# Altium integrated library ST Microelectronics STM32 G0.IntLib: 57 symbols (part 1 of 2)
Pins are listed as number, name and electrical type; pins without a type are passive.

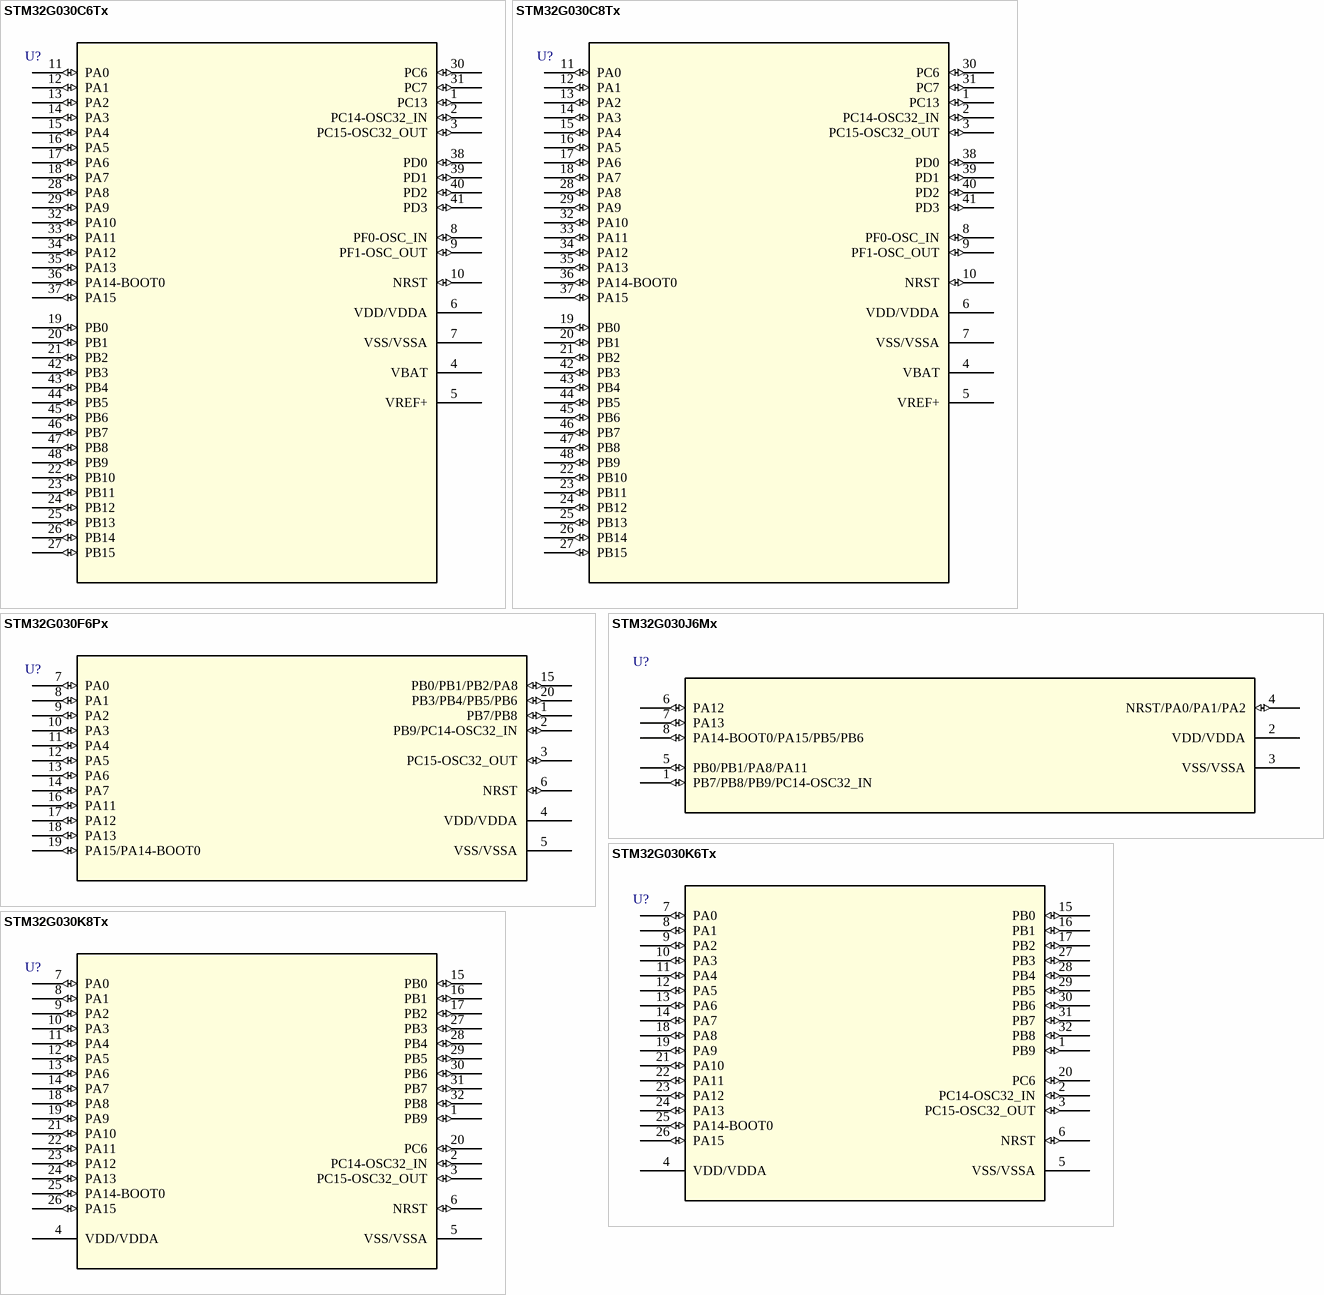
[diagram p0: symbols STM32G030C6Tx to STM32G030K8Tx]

## STM32G030C6Tx
designator U?
The STM32G030x6/x8 mainstream microcontrollers are based on high-performance Arm® Cortex®-M0+ 32-bit RISC core operating at up to 64 MHz frequency. / 32K Flash and 8K RAM with 48pin LQFP 7x7x0.55  package; Manufacturer_Part_Number: stm32g0_lqfp48_t2; Vendor: STMicroelectronics
footprint LQFP48
pins: 1 PC13 (io), 2 PC14-OSC32_IN (io), 3 PC15-OSC32_OUT (io), 4 VBAT (power), 5 VREF+ (power), 6 VDD/VDDA (power), 7 VSS/VSSA (power), 8 PF0-OSC_IN (io), 9 PF1-OSC_OUT (io), 10 NRST (io), 11 PA0 (io), 12 PA1 (io), 13 PA2 (io), 14 PA3 (io), 15 PA4 (io), 16 PA5 (io), 17 PA6 (io), 18 PA7 (io), 19 PB0 (io), 20 PB1 (io), 21 PB2 (io), 22 PB10 (io), 23 PB11 (io), 24 PB12 (io), 25 PB13 (io), 26 PB14 (io), 27 PB15 (io), 28 PA8 (io), 29 PA9 (io), 30 PC6 (io), 31 PC7 (io), 32 PA10 (io), 33 PA11 (io), 34 PA12 (io), 35 PA13 (io), 36 PA14-BOOT0 (io), 37 PA15 (io), 38 PD0 (io), 39 PD1 (io), 40 PD2 (io), 41 PD3 (io), 42 PB3 (io), 43 PB4 (io), 44 PB5 (io), 45 PB6 (io), 46 PB7 (io), 47 PB8 (io), 48 PB9 (io)

## STM32G030C8Tx
designator U?
The STM32G030x6/x8 mainstream microcontrollers are based on high-performance Arm® Cortex®-M0+ 32-bit RISC core operating at up to 64 MHz frequency. / 64K Flash and 8K RAM with 48pin LQFP 7x7x0.55 package; Manufacturer_Part_Number: stm32g0_lqfp48_t2; Vendor: STMicroelectronics
footprint LQFP48
pins: 1 PC13 (io), 2 PC14-OSC32_IN (io), 3 PC15-OSC32_OUT (io), 4 VBAT (power), 5 VREF+ (power), 6 VDD/VDDA (power), 7 VSS/VSSA (power), 8 PF0-OSC_IN (io), 9 PF1-OSC_OUT (io), 10 NRST (io), 11 PA0 (io), 12 PA1 (io), 13 PA2 (io), 14 PA3 (io), 15 PA4 (io), 16 PA5 (io), 17 PA6 (io), 18 PA7 (io), 19 PB0 (io), 20 PB1 (io), 21 PB2 (io), 22 PB10 (io), 23 PB11 (io), 24 PB12 (io), 25 PB13 (io), 26 PB14 (io), 27 PB15 (io), 28 PA8 (io), 29 PA9 (io), 30 PC6 (io), 31 PC7 (io), 32 PA10 (io), 33 PA11 (io), 34 PA12 (io), 35 PA13 (io), 36 PA14-BOOT0 (io), 37 PA15 (io), 38 PD0 (io), 39 PD1 (io), 40 PD2 (io), 41 PD3 (io), 42 PB3 (io), 43 PB4 (io), 44 PB5 (io), 45 PB6 (io), 46 PB7 (io), 47 PB8 (io), 48 PB9 (io)

## STM32G030F6Px
designator U?
The STM32G030x6/x8 mainstream microcontrollers are based on high-performance Arm® Cortex®-M0+ 32-bit RISC core operating at up to 64 MHz frequency. / 32K Flash and 8K RAM with 20pin TSSOP 6.4x4.4mm package; Manufacturer_Part_Number: stm32g0_tssop20_t1; Vendor: STMicroelectronics
footprint TSSOP20
pins: 1 PB7/PB8 (io), 2 PB9/PC14-OSC32_IN (io), 3 PC15-OSC32_OUT (io), 4 VDD/VDDA (power), 5 VSS/VSSA (power), 6 NRST (io), 7 PA0 (io), 8 PA1 (io), 9 PA2 (io), 10 PA3 (io), 11 PA4 (io), 12 PA5 (io), 13 PA6 (io), 14 PA7 (io), 15 PB0/PB1/PB2/PA8 (io), 16 PA11 (io), 17 PA12 (io), 18 PA13 (io), 19 PA15/PA14-BOOT0 (io), 20 PB3/PB4/PB5/PB6 (io)

## STM32G030J6Mx
designator U?
The STM32G030x6/x8 mainstream microcontrollers are based on high-performance Arm® Cortex®-M0+ 32-bit RISC core operating at up to 64 MHz frequency. / 32K Flash and 8K RAM with 8pin SON 4.9x6 mm package; Manufacturer_Part_Number: stm32g0_so8_t1; Vendor: STMicroelectronics
footprint SO-8
pins: 1 PB7/PB8/PB9/PC14-OSC32_IN (io), 2 VDD/VDDA (power), 3 VSS/VSSA (power), 4 NRST/PA0/PA1/PA2 (io), 5 PB0/PB1/PA8/PA11 (io), 6 PA12 (io), 7 PA13 (io), 8 PA14-BOOT0/PA15/PB5/PB6 (io)

## STM32G030K6Tx
designator U?
The STM32G030x6/x8 mainstream microcontrollers are based on high-performance Arm® Cortex®-M0+ 32-bit RISC core operating at up to 64 MHz frequency. / 32K Flash and 8K RAM with 32pin LQFP 7x7x1.4 package; Manufacturer_Part_Number: STM32G0_LQFP32_T2; Vendor: STMicroelectronics
footprint LQFP-32
pins: 1 PB9 (io), 2 PC14-OSC32_IN (io), 3 PC15-OSC32_OUT (io), 4 VDD/VDDA (power), 5 VSS/VSSA (power), 6 NRST (io), 7 PA0 (io), 8 PA1 (io), 9 PA2 (io), 10 PA3 (io), 11 PA4 (io), 12 PA5 (io), 13 PA6 (io), 14 PA7 (io), 15 PB0 (io), 16 PB1 (io), 17 PB2 (io), 18 PA8 (io), 19 PA9 (io), 20 PC6 (io), 21 PA10 (io), 22 PA11 (io), 23 PA12 (io), 24 PA13 (io), 25 PA14-BOOT0 (io), 26 PA15 (io), 27 PB3 (io), 28 PB4 (io), 29 PB5 (io), 30 PB6 (io), 31 PB7 (io), 32 PB8 (io)

## STM32G030K8Tx
designator U?
The STM32G030x6/x8 mainstream microcontrollers are based on high-performance Arm® Cortex®-M0+ 32-bit RISC core operating at up to 64 MHz frequency. / 64K Flash and 8K RAM with 32pin LQFP 7x7x1.4 package; Manufacturer_Part_Number: STM32G0_LQFP32_T2; Vendor: STMicroelectronics
footprint LQFP-32
pins: 1 PB9 (io), 2 PC14-OSC32_IN (io), 3 PC15-OSC32_OUT (io), 4 VDD/VDDA (power), 5 VSS/VSSA (power), 6 NRST (io), 7 PA0 (io), 8 PA1 (io), 9 PA2 (io), 10 PA3 (io), 11 PA4 (io), 12 PA5 (io), 13 PA6 (io), 14 PA7 (io), 15 PB0 (io), 16 PB1 (io), 17 PB2 (io), 18 PA8 (io), 19 PA9 (io), 20 PC6 (io), 21 PA10 (io), 22 PA11 (io), 23 PA12 (io), 24 PA13 (io), 25 PA14-BOOT0 (io), 26 PA15 (io), 27 PB3 (io), 28 PB4 (io), 29 PB5 (io), 30 PB6 (io), 31 PB7 (io), 32 PB8 (io)

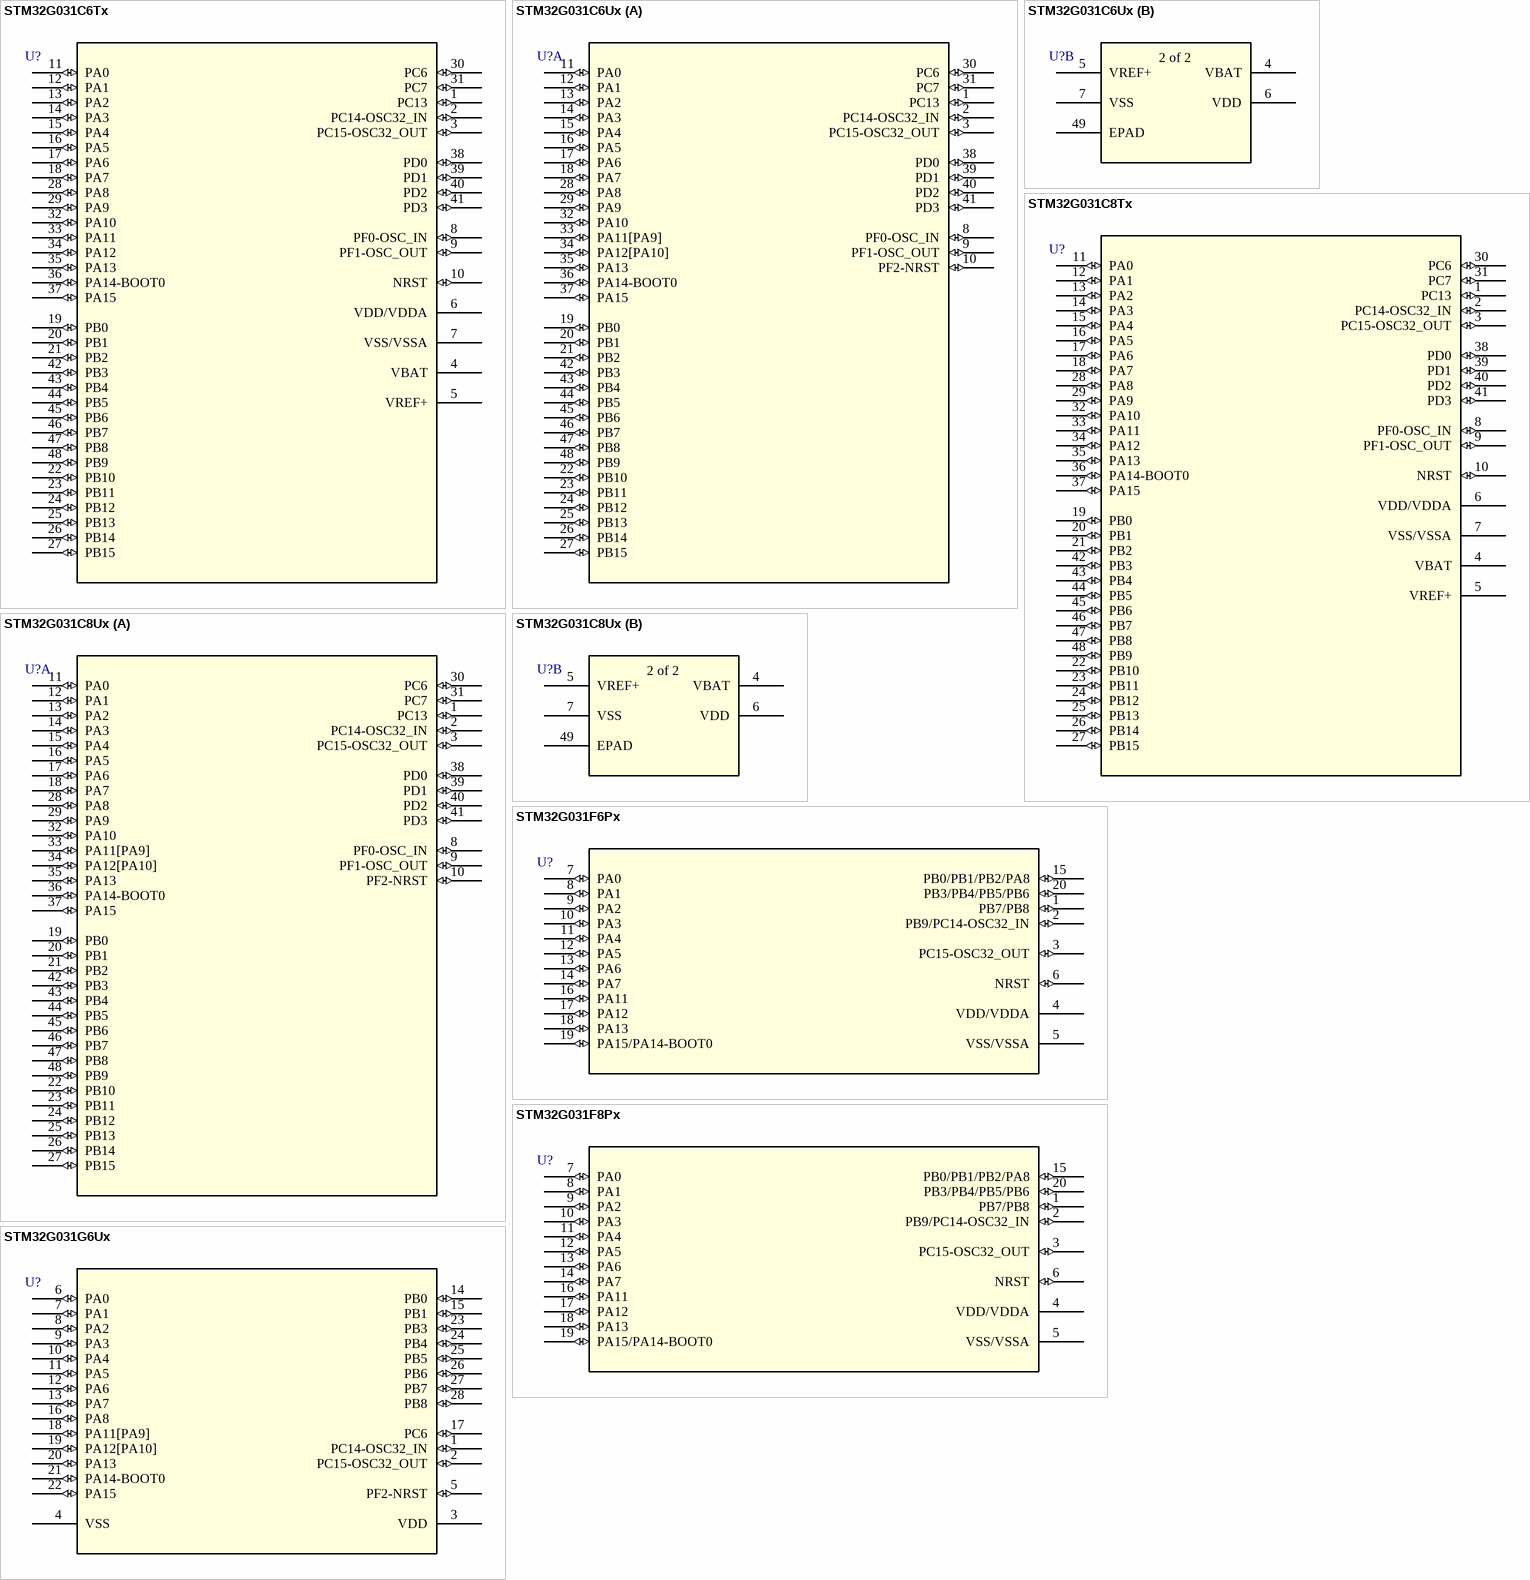
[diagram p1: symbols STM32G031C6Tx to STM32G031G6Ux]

## STM32G031C6Tx
designator U?
The STM32G031x4/x6/x8 mainstream microcontrollers are based on high-performance Arm® Cortex®-M0+ 32-bit RISC core operating at up to 64 MHz frequency. / 32 Kbytes of Flash program memory and 8 Kbytes of SRAM. With 48pin LQFP 7x7x1.4 package; Manufacturer_Part_Number: stm32g0_lqfp48_t2; Vendor: STMicroelectronics
footprint LQFP48
pins: 1 PC13 (io), 2 PC14-OSC32_IN (io), 3 PC15-OSC32_OUT (io), 4 VBAT (power), 5 VREF+ (power), 6 VDD/VDDA (power), 7 VSS/VSSA (power), 8 PF0-OSC_IN (io), 9 PF1-OSC_OUT (io), 10 NRST (io), 11 PA0 (io), 12 PA1 (io), 13 PA2 (io), 14 PA3 (io), 15 PA4 (io), 16 PA5 (io), 17 PA6 (io), 18 PA7 (io), 19 PB0 (io), 20 PB1 (io), 21 PB2 (io), 22 PB10 (io), 23 PB11 (io), 24 PB12 (io), 25 PB13 (io), 26 PB14 (io), 27 PB15 (io), 28 PA8 (io), 29 PA9 (io), 30 PC6 (io), 31 PC7 (io), 32 PA10 (io), 33 PA11 (io), 34 PA12 (io), 35 PA13 (io), 36 PA14-BOOT0 (io), 37 PA15 (io), 38 PD0 (io), 39 PD1 (io), 40 PD2 (io), 41 PD3 (io), 42 PB3 (io), 43 PB4 (io), 44 PB5 (io), 45 PB6 (io), 46 PB7 (io), 47 PB8 (io), 48 PB9 (io)

## STM32G031C6Ux
designator U?
The STM32G031x4/x6/x8 mainstream microcontrollers are based on high-performance Arm® Cortex®-M0+ 32-bit RISC core operating at up to 64 MHz frequency. / 32 Kbytes of Flash program memory and 8 Kbytes of SRAM. With 48pin UFQFPN 7x7x0.55 package; Manufacturer_Part_Number: stm32g0_ufqfpn48_t1; Built_By: EMA_Jessica; Vendor: STMicroelectronics
footprint UFQFPN48-7x7mm
part A pins: 1 PC13 (io), 2 PC14-OSC32_IN (io), 3 PC15-OSC32_OUT (io), 8 PF0-OSC_IN (io), 9 PF1-OSC_OUT (io), 10 PF2-NRST (io), 11 PA0 (io), 12 PA1 (io), 13 PA2 (io), 14 PA3 (io), 15 PA4 (io), 16 PA5 (io), 17 PA6 (io), 18 PA7 (io), 19 PB0 (io), 20 PB1 (io), 21 PB2 (io), 22 PB10 (io), 23 PB11 (io), 24 PB12 (io), 25 PB13 (io), 26 PB14 (io), 27 PB15 (io), 28 PA8 (io), 29 PA9 (io), 30 PC6 (io), 31 PC7 (io), 32 PA10 (io), 33 PA11[PA9] (io), 34 PA12[PA10] (io), 35 PA13 (io), 36 PA14-BOOT0 (io), 37 PA15 (io), 38 PD0 (io), 39 PD1 (io), 40 PD2 (io), 41 PD3 (io), 42 PB3 (io), 43 PB4 (io), 44 PB5 (io), 45 PB6 (io), 46 PB7 (io), 47 PB8 (io), 48 PB9 (io)
part B pins: 4 VBAT (power), 5 VREF+ (power), 6 VDD (power), 7 VSS (power), 49 EPAD

## STM32G031C8Tx
designator U?
The STM32G031x4/x6/x8 mainstream microcontrollers are based on high-performance Arm® Cortex®-M0+ 32-bit RISC core operating at up to 64 MHz frequency. / 64 Kbytes of Flash program memory and 8 Kbytes of SRAM. With 48pin LQFP  7x7x1.4  package; Manufacturer_Part_Number: stm32g0_lqfp48_t2; Vendor: STMicroelectronics
footprint LQFP48
pins: 1 PC13 (io), 2 PC14-OSC32_IN (io), 3 PC15-OSC32_OUT (io), 4 VBAT (power), 5 VREF+ (power), 6 VDD/VDDA (power), 7 VSS/VSSA (power), 8 PF0-OSC_IN (io), 9 PF1-OSC_OUT (io), 10 NRST (io), 11 PA0 (io), 12 PA1 (io), 13 PA2 (io), 14 PA3 (io), 15 PA4 (io), 16 PA5 (io), 17 PA6 (io), 18 PA7 (io), 19 PB0 (io), 20 PB1 (io), 21 PB2 (io), 22 PB10 (io), 23 PB11 (io), 24 PB12 (io), 25 PB13 (io), 26 PB14 (io), 27 PB15 (io), 28 PA8 (io), 29 PA9 (io), 30 PC6 (io), 31 PC7 (io), 32 PA10 (io), 33 PA11 (io), 34 PA12 (io), 35 PA13 (io), 36 PA14-BOOT0 (io), 37 PA15 (io), 38 PD0 (io), 39 PD1 (io), 40 PD2 (io), 41 PD3 (io), 42 PB3 (io), 43 PB4 (io), 44 PB5 (io), 45 PB6 (io), 46 PB7 (io), 47 PB8 (io), 48 PB9 (io)

## STM32G031C8Ux
designator U?
The STM32G031x4/x6/x8 mainstream microcontrollers are based on high-performance Arm® Cortex®-M0+ 32-bit RISC core operating at up to 64 MHz frequency. / 64 Kbytes of Flash program memory and 8 Kbytes of SRAM. With 48pin UFQFPN  7x7x0.55 package; Manufacturer_Part_Number: stm32g0_ufqfpn48_t1; Built_By: EMA_Jessica; Vendor: STMicroelectronics
footprint UFQFPN48-7x7mm
part A pins: 1 PC13 (io), 2 PC14-OSC32_IN (io), 3 PC15-OSC32_OUT (io), 8 PF0-OSC_IN (io), 9 PF1-OSC_OUT (io), 10 PF2-NRST (io), 11 PA0 (io), 12 PA1 (io), 13 PA2 (io), 14 PA3 (io), 15 PA4 (io), 16 PA5 (io), 17 PA6 (io), 18 PA7 (io), 19 PB0 (io), 20 PB1 (io), 21 PB2 (io), 22 PB10 (io), 23 PB11 (io), 24 PB12 (io), 25 PB13 (io), 26 PB14 (io), 27 PB15 (io), 28 PA8 (io), 29 PA9 (io), 30 PC6 (io), 31 PC7 (io), 32 PA10 (io), 33 PA11[PA9] (io), 34 PA12[PA10] (io), 35 PA13 (io), 36 PA14-BOOT0 (io), 37 PA15 (io), 38 PD0 (io), 39 PD1 (io), 40 PD2 (io), 41 PD3 (io), 42 PB3 (io), 43 PB4 (io), 44 PB5 (io), 45 PB6 (io), 46 PB7 (io), 47 PB8 (io), 48 PB9 (io)
part B pins: 4 VBAT (power), 5 VREF+ (power), 6 VDD (power), 7 VSS (power), 49 EPAD

## STM32G031F6Px
designator U?
The STM32G031x4/x6/x8 mainstream microcontrollers are based on high-performance Arm® Cortex®-M0+ 32-bit RISC core operating at up to 64 MHz frequency. / 32 Kbytes of Flash program memory and 8 Kbytes of SRAM. With 20pin TSSOP 6.4x4.4 package; Manufacturer_Part_Number: stm32g0_tssop20_t1; Vendor: STMicroelectronics
footprint TSSOP20
pins: 1 PB7/PB8 (io), 2 PB9/PC14-OSC32_IN (io), 3 PC15-OSC32_OUT (io), 4 VDD/VDDA (power), 5 VSS/VSSA (power), 6 NRST (io), 7 PA0 (io), 8 PA1 (io), 9 PA2 (io), 10 PA3 (io), 11 PA4 (io), 12 PA5 (io), 13 PA6 (io), 14 PA7 (io), 15 PB0/PB1/PB2/PA8 (io), 16 PA11 (io), 17 PA12 (io), 18 PA13 (io), 19 PA15/PA14-BOOT0 (io), 20 PB3/PB4/PB5/PB6 (io)

## STM32G031F8Px
designator U?
The STM32G031x4/x6/x8 mainstream microcontrollers are based on high-performance Arm® Cortex®-M0+ 32-bit RISC core operating at up to 64 MHz frequency. / 64 Kbytes of Flash program memory and 8 Kbytes of SRAM. With 20pin TSSOP 6.4x4.4 package; Manufacturer_Part_Number: stm32g0_tssop20_t1; Vendor: STMicroelectronics
footprint TSSOP20
pins: 1 PB7/PB8 (io), 2 PB9/PC14-OSC32_IN (io), 3 PC15-OSC32_OUT (io), 4 VDD/VDDA (power), 5 VSS/VSSA (power), 6 NRST (io), 7 PA0 (io), 8 PA1 (io), 9 PA2 (io), 10 PA3 (io), 11 PA4 (io), 12 PA5 (io), 13 PA6 (io), 14 PA7 (io), 15 PB0/PB1/PB2/PA8 (io), 16 PA11 (io), 17 PA12 (io), 18 PA13 (io), 19 PA15/PA14-BOOT0 (io), 20 PB3/PB4/PB5/PB6 (io)

## STM32G031G6Ux
designator U?
The STM32G031x4/x6/x8 mainstream microcontrollers are based on high-performance Arm® Cortex®-M0+ 32-bit RISC core operating at up to 64 MHz frequency. / 32 Kbytes of Flash program memory and 8 Kbytes of SRAM. With 28pin UFQFPN 4x4x0.55 package; Manufacturer_Part_Number: stm32g0_ufqfpn28_t1; Built_By: EMA_Jessica; Vendor: STMicroelectronics
footprint UFQFPN-28
pins: 1 PC14-OSC32_IN (io), 2 PC15-OSC32_OUT (io), 3 VDD (power), 4 VSS (power), 5 PF2-NRST (io), 6 PA0 (io), 7 PA1 (io), 8 PA2 (io), 9 PA3 (io), 10 PA4 (io), 11 PA5 (io), 12 PA6 (io), 13 PA7 (io), 14 PB0 (io), 15 PB1 (io), 16 PA8 (io), 17 PC6 (io), 18 PA11[PA9] (io), 19 PA12[PA10] (io), 20 PA13 (io), 21 PA14-BOOT0 (io), 22 PA15 (io), 23 PB3 (io), 24 PB4 (io), 25 PB5 (io), 26 PB6 (io), 27 PB7 (io), 28 PB8 (io)

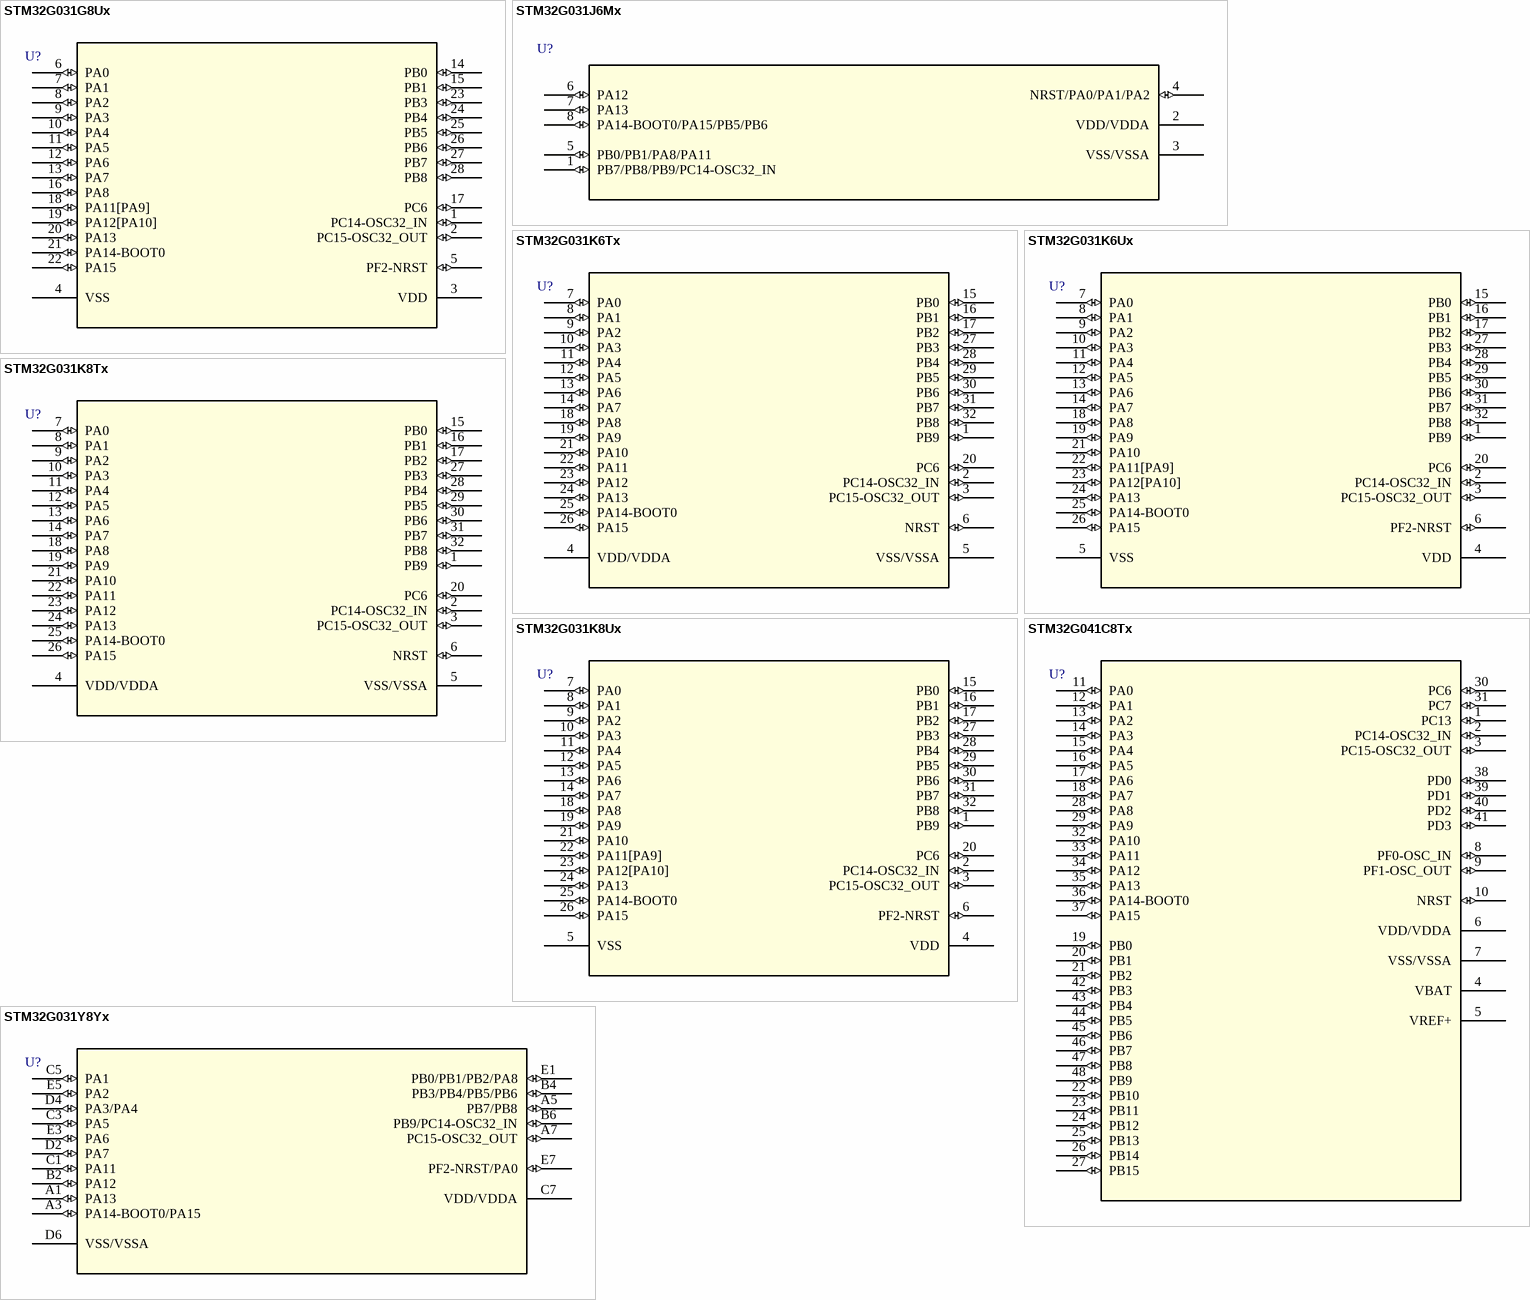
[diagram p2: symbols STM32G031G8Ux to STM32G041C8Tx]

## STM32G031G8Ux
designator U?
The STM32G031x4/x6/x8 mainstream microcontrollers are based on high-performance Arm® Cortex®-M0+ 32-bit RISC core operating at up to 64 MHz frequency. / 64 Kbytes of Flash program memory and 8 Kbytes of SRAM. With 28pin UFQFPN 4x4x0.55 package; Manufacturer_Part_Number: stm32g0_ufqfpn28_t1; Built_By: EMA_Jessica; Vendor: STMicroelectronics
footprint UFQFPN-28
pins: 1 PC14-OSC32_IN (io), 2 PC15-OSC32_OUT (io), 3 VDD (power), 4 VSS (power), 5 PF2-NRST (io), 6 PA0 (io), 7 PA1 (io), 8 PA2 (io), 9 PA3 (io), 10 PA4 (io), 11 PA5 (io), 12 PA6 (io), 13 PA7 (io), 14 PB0 (io), 15 PB1 (io), 16 PA8 (io), 17 PC6 (io), 18 PA11[PA9] (io), 19 PA12[PA10] (io), 20 PA13 (io), 21 PA14-BOOT0 (io), 22 PA15 (io), 23 PB3 (io), 24 PB4 (io), 25 PB5 (io), 26 PB6 (io), 27 PB7 (io), 28 PB8 (io)

## STM32G031J6Mx
designator U?
The STM32G031x4/x6/x8 mainstream microcontrollers are based on high-performance Arm® Cortex®-M0+ 32-bit RISC core operating at up to 64 MHz frequency. / 32 Kbytes of Flash program memory and 8 Kbytes of SRAM. With 28pin UFQFPN 4x4x0.55 package; Manufacturer_Part_Number: stm32g0_so8_t1; Vendor: STMicroelectronics
footprint SO-8
pins: 1 PB7/PB8/PB9/PC14-OSC32_IN (io), 2 VDD/VDDA (power), 3 VSS/VSSA (power), 4 NRST/PA0/PA1/PA2 (io), 5 PB0/PB1/PA8/PA11 (io), 6 PA12 (io), 7 PA13 (io), 8 PA14-BOOT0/PA15/PB5/PB6 (io)

## STM32G031K6Tx
designator U?
The STM32G031x4/x6/x8 mainstream microcontrollers are based on high-performance Arm® Cortex®-M0+ 32-bit RISC core operating at up to 64 MHz frequency. / 32 Kbytes of Flash program memory and 8 Kbytes of SRAM. With 32pin LQFP 7x7x1.4 package; Manufacturer_Part_Number: STM32G0_LQFP32_T2; Vendor: STMicroelectronics
footprint LQFP-32
pins: 1 PB9 (io), 2 PC14-OSC32_IN (io), 3 PC15-OSC32_OUT (io), 4 VDD/VDDA (power), 5 VSS/VSSA (power), 6 NRST (io), 7 PA0 (io), 8 PA1 (io), 9 PA2 (io), 10 PA3 (io), 11 PA4 (io), 12 PA5 (io), 13 PA6 (io), 14 PA7 (io), 15 PB0 (io), 16 PB1 (io), 17 PB2 (io), 18 PA8 (io), 19 PA9 (io), 20 PC6 (io), 21 PA10 (io), 22 PA11 (io), 23 PA12 (io), 24 PA13 (io), 25 PA14-BOOT0 (io), 26 PA15 (io), 27 PB3 (io), 28 PB4 (io), 29 PB5 (io), 30 PB6 (io), 31 PB7 (io), 32 PB8 (io)

## STM32G031K6Ux
designator U?
The STM32G031x4/x6/x8 mainstream microcontrollers are based on high-performance Arm® Cortex®-M0+ 32-bit RISC core operating at up to 64 MHz frequency. / 32 Kbytes of Flash program memory and 8 Kbytes of SRAM. With 32pin UFQFPN  5x5x0.55  package; Manufacturer_Part_Number: stm32g0_ufqfpn32_t1; Built_By: EMA_Jessica; Vendor: STMicroelectronics
footprint UFQFPN-32
pins: 1 PB9 (io), 2 PC14-OSC32_IN (io), 3 PC15-OSC32_OUT (io), 4 VDD (power), 5 VSS (power), 6 PF2-NRST (io), 7 PA0 (io), 8 PA1 (io), 9 PA2 (io), 10 PA3 (io), 11 PA4 (io), 12 PA5 (io), 13 PA6 (io), 14 PA7 (io), 15 PB0 (io), 16 PB1 (io), 17 PB2 (io), 18 PA8 (io), 19 PA9 (io), 20 PC6 (io), 21 PA10 (io), 22 PA11[PA9] (io), 23 PA12[PA10] (io), 24 PA13 (io), 25 PA14-BOOT0 (io), 26 PA15 (io), 27 PB3 (io), 28 PB4 (io), 29 PB5 (io), 30 PB6 (io), 31 PB7 (io), 32 PB8 (io)

## STM32G031K8Tx
designator U?
The STM32G031x4/x6/x8 mainstream microcontrollers are based on high-performance Arm® Cortex®-M0+ 32-bit RISC core operating at up to 64 MHz frequency. / 64 Kbytes of Flash program memory and 8 Kbytes of SRAM. With 32pin LQFP 7x7x1.4 package; Manufacturer_Part_Number: STM32G0_LQFP32_T2; Vendor: STMicroelectronics
footprint LQFP-32
pins: 1 PB9 (io), 2 PC14-OSC32_IN (io), 3 PC15-OSC32_OUT (io), 4 VDD/VDDA (power), 5 VSS/VSSA (power), 6 NRST (io), 7 PA0 (io), 8 PA1 (io), 9 PA2 (io), 10 PA3 (io), 11 PA4 (io), 12 PA5 (io), 13 PA6 (io), 14 PA7 (io), 15 PB0 (io), 16 PB1 (io), 17 PB2 (io), 18 PA8 (io), 19 PA9 (io), 20 PC6 (io), 21 PA10 (io), 22 PA11 (io), 23 PA12 (io), 24 PA13 (io), 25 PA14-BOOT0 (io), 26 PA15 (io), 27 PB3 (io), 28 PB4 (io), 29 PB5 (io), 30 PB6 (io), 31 PB7 (io), 32 PB8 (io)

## STM32G031K8Ux
designator U?
The STM32G031x4/x6/x8 mainstream microcontrollers are based on high-performance Arm® Cortex®-M0+ 32-bit RISC core operating at up to 64 MHz frequency. / 64 Kbytes of Flash program memory and 8 Kbytes of SRAM. With 32pin UFQFPN  5x5x0.55  package; Manufacturer_Part_Number: stm32g0_ufqfpn32_t1; Built_By: EMA_Jessica; Vendor: STMicroelectronics
footprint UFQFPN-32
pins: 1 PB9 (io), 2 PC14-OSC32_IN (io), 3 PC15-OSC32_OUT (io), 4 VDD (power), 5 VSS (power), 6 PF2-NRST (io), 7 PA0 (io), 8 PA1 (io), 9 PA2 (io), 10 PA3 (io), 11 PA4 (io), 12 PA5 (io), 13 PA6 (io), 14 PA7 (io), 15 PB0 (io), 16 PB1 (io), 17 PB2 (io), 18 PA8 (io), 19 PA9 (io), 20 PC6 (io), 21 PA10 (io), 22 PA11[PA9] (io), 23 PA12[PA10] (io), 24 PA13 (io), 25 PA14-BOOT0 (io), 26 PA15 (io), 27 PB3 (io), 28 PB4 (io), 29 PB5 (io), 30 PB6 (io), 31 PB7 (io), 32 PB8 (io)

## STM32G031Y8Yx
designator U?
The STM32G031x4/x6/x8 mainstream microcontrollers are based on high-performance Arm® Cortex®-M0+ 32-bit RISC core operating at up to 64 MHz frequency. / 64 Kbytes of Flash program memory and 8 Kbytes of SRAM. With 18pin WLCSP  1.86x2.14  package; Manufacturer_Part_Number: STM32G0_WLCSP18_T1; Vendor: STMicroelectronics
footprint WLCSP18
pins: A1 PA13 (io), A3 PA14-BOOT0/PA15 (io), A5 PB7/PB8 (io), A7 PC15-OSC32_OUT (io), B2 PA12 (io), B4 PB3/PB4/PB5/PB6 (io), B6 PB9/PC14-OSC32_IN (io), C1 PA11 (io), C3 PA5 (io), C5 PA1 (io), C7 VDD/VDDA (power), D2 PA7 (io), D4 PA3/PA4 (io), D6 VSS/VSSA (power), E1 PB0/PB1/PB2/PA8 (io), E3 PA6 (io), E5 PA2 (io), E7 PF2-NRST/PA0 (io)

## STM32G041C8Tx
designator U?
The STM32G041x6/x8 mainstream microcontrollers are based on high-performance Arm® Cortex®-M0+ 32-bit RISC core operating at up to 64 MHz frequency. / 64 Kbytes of Flash program memory and 8 Kbytes of SRAM. With 48pin LQFP  7x7x1.4  package; Manufacturer_Part_Number: stm32g0_lqfp48_t2; Vendor: STMicroelectronics
footprint LQFP48
pins: 1 PC13 (io), 2 PC14-OSC32_IN (io), 3 PC15-OSC32_OUT (io), 4 VBAT (power), 5 VREF+ (power), 6 VDD/VDDA (power), 7 VSS/VSSA (power), 8 PF0-OSC_IN (io), 9 PF1-OSC_OUT (io), 10 NRST (io), 11 PA0 (io), 12 PA1 (io), 13 PA2 (io), 14 PA3 (io), 15 PA4 (io), 16 PA5 (io), 17 PA6 (io), 18 PA7 (io), 19 PB0 (io), 20 PB1 (io), 21 PB2 (io), 22 PB10 (io), 23 PB11 (io), 24 PB12 (io), 25 PB13 (io), 26 PB14 (io), 27 PB15 (io), 28 PA8 (io), 29 PA9 (io), 30 PC6 (io), 31 PC7 (io), 32 PA10 (io), 33 PA11 (io), 34 PA12 (io), 35 PA13 (io), 36 PA14-BOOT0 (io), 37 PA15 (io), 38 PD0 (io), 39 PD1 (io), 40 PD2 (io), 41 PD3 (io), 42 PB3 (io), 43 PB4 (io), 44 PB5 (io), 45 PB6 (io), 46 PB7 (io), 47 PB8 (io), 48 PB9 (io)

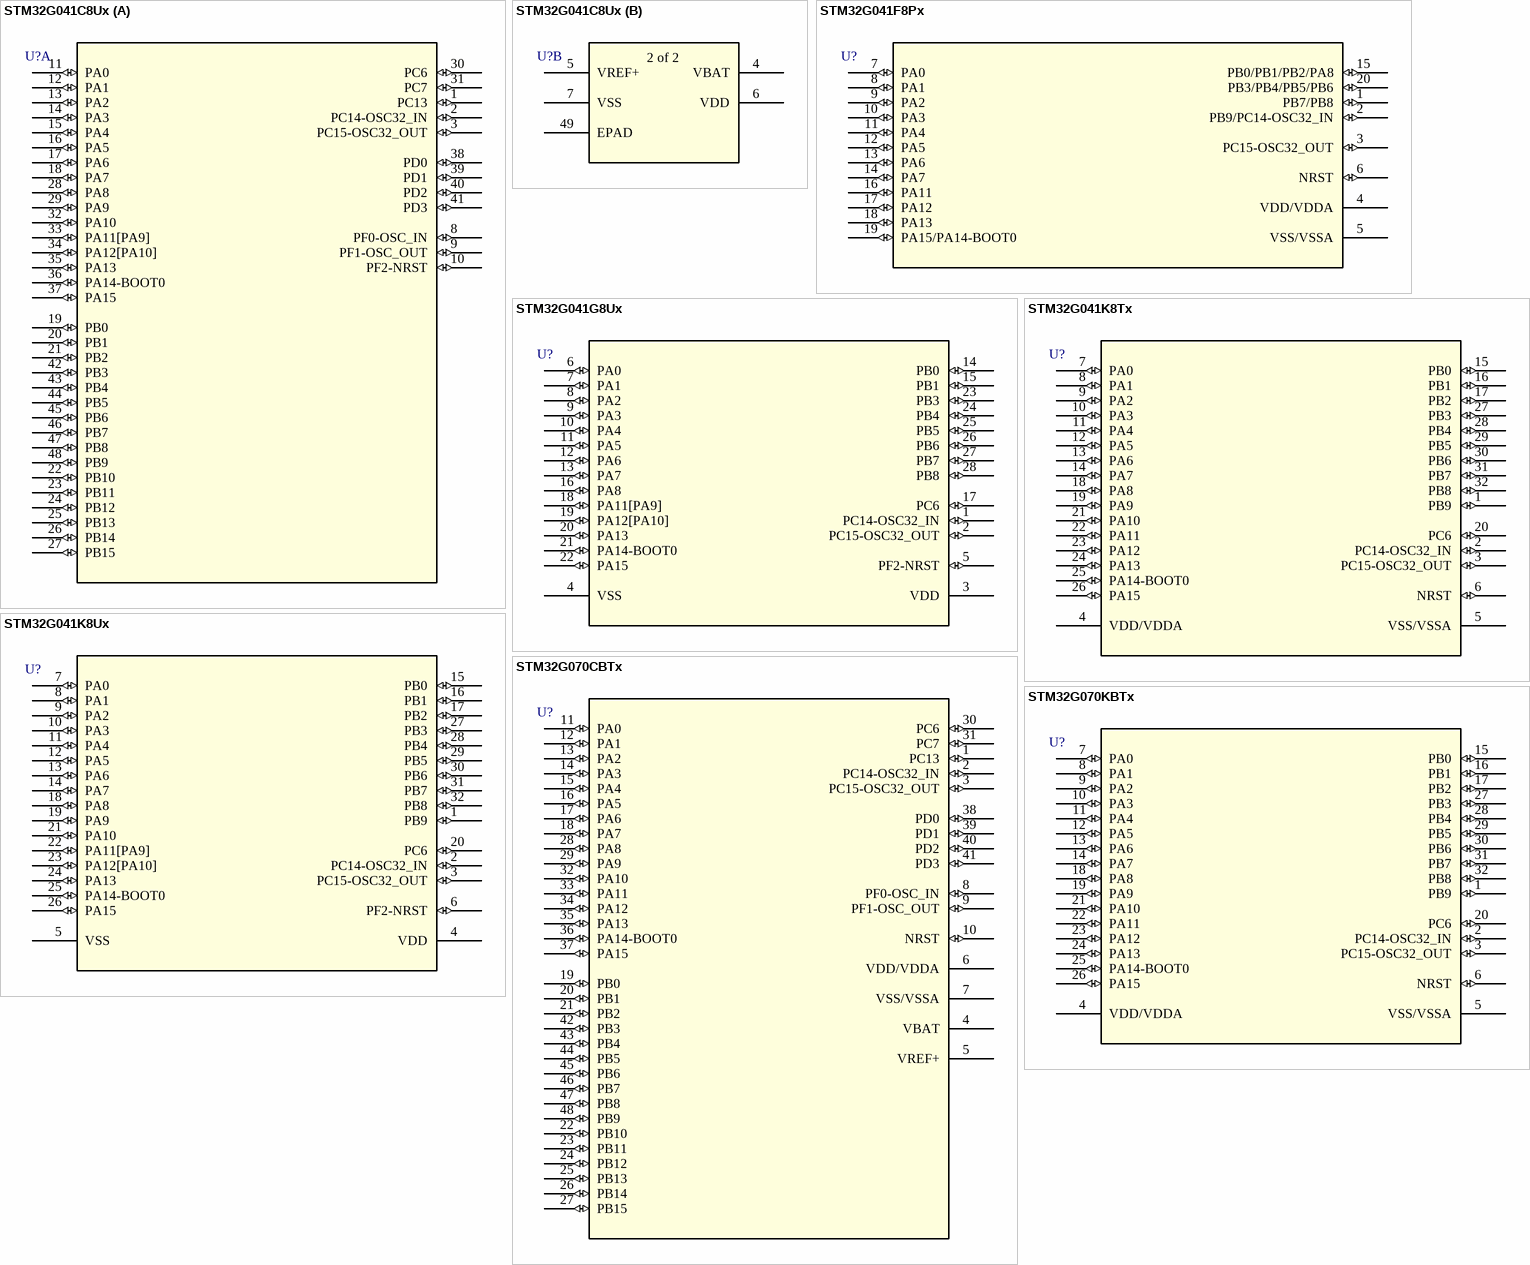
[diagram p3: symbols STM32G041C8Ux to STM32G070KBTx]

## STM32G041C8Ux
designator U?
The STM32G041x6/x8 mainstream microcontrollers are based on high-performance Arm® Cortex®-M0+ 32-bit RISC core operating at up to 64 MHz frequency. / 64 Kbytes of Flash program memory and 8 Kbytes of SRAM.  With 48pin UFQFPN  7x7x0.55 package; Manufacturer_Part_Number: stm32g0_ufqfpn48_t1; Built_By: EMA_Jessica; Vendor: STMicroelectronics
footprint UFQFPN48-7x7mm
part A pins: 1 PC13 (io), 2 PC14-OSC32_IN (io), 3 PC15-OSC32_OUT (io), 8 PF0-OSC_IN (io), 9 PF1-OSC_OUT (io), 10 PF2-NRST (io), 11 PA0 (io), 12 PA1 (io), 13 PA2 (io), 14 PA3 (io), 15 PA4 (io), 16 PA5 (io), 17 PA6 (io), 18 PA7 (io), 19 PB0 (io), 20 PB1 (io), 21 PB2 (io), 22 PB10 (io), 23 PB11 (io), 24 PB12 (io), 25 PB13 (io), 26 PB14 (io), 27 PB15 (io), 28 PA8 (io), 29 PA9 (io), 30 PC6 (io), 31 PC7 (io), 32 PA10 (io), 33 PA11[PA9] (io), 34 PA12[PA10] (io), 35 PA13 (io), 36 PA14-BOOT0 (io), 37 PA15 (io), 38 PD0 (io), 39 PD1 (io), 40 PD2 (io), 41 PD3 (io), 42 PB3 (io), 43 PB4 (io), 44 PB5 (io), 45 PB6 (io), 46 PB7 (io), 47 PB8 (io), 48 PB9 (io)
part B pins: 4 VBAT (power), 5 VREF+ (power), 6 VDD (power), 7 VSS (power), 49 EPAD

## STM32G041F8Px
designator U?
The STM32G041x6/x8 mainstream microcontrollers are based on high-performance Arm® Cortex®-M0+ 32-bit RISC core operating at up to 64 MHz frequency. / 64 Kbytes of Flash program memory and 8 Kbytes of SRAM.  With 20pin TSSOP 6.4x4.4 package; Manufacturer_Part_Number: stm32g0_tssop20_t1; Vendor: STMicroelectronics
footprint TSSOP20
pins: 1 PB7/PB8 (io), 2 PB9/PC14-OSC32_IN (io), 3 PC15-OSC32_OUT (io), 4 VDD/VDDA (power), 5 VSS/VSSA (power), 6 NRST (io), 7 PA0 (io), 8 PA1 (io), 9 PA2 (io), 10 PA3 (io), 11 PA4 (io), 12 PA5 (io), 13 PA6 (io), 14 PA7 (io), 15 PB0/PB1/PB2/PA8 (io), 16 PA11 (io), 17 PA12 (io), 18 PA13 (io), 19 PA15/PA14-BOOT0 (io), 20 PB3/PB4/PB5/PB6 (io)

## STM32G041G8Ux
designator U?
The STM32G041x6/x8 mainstream microcontrollers are based on high-performance Arm® Cortex®-M0+ 32-bit RISC core operating at up to 64 MHz frequency. / 64 Kbytes of Flash program memory and 8 Kbytes of SRAM. With 28pin UFQFPN 4x4x0.55 package; Manufacturer_Part_Number: stm32g0_ufqfpn28_t1; Built_By: EMA_Jessica; Vendor: STMicroelectronics
footprint UFQFPN-28
pins: 1 PC14-OSC32_IN (io), 2 PC15-OSC32_OUT (io), 3 VDD (power), 4 VSS (power), 5 PF2-NRST (io), 6 PA0 (io), 7 PA1 (io), 8 PA2 (io), 9 PA3 (io), 10 PA4 (io), 11 PA5 (io), 12 PA6 (io), 13 PA7 (io), 14 PB0 (io), 15 PB1 (io), 16 PA8 (io), 17 PC6 (io), 18 PA11[PA9] (io), 19 PA12[PA10] (io), 20 PA13 (io), 21 PA14-BOOT0 (io), 22 PA15 (io), 23 PB3 (io), 24 PB4 (io), 25 PB5 (io), 26 PB6 (io), 27 PB7 (io), 28 PB8 (io)

## STM32G041K8Tx
designator U?
The STM32G041x6/x8 mainstream microcontrollers are based on high-performance Arm® Cortex®-M0+ 32-bit RISC core operating at up to 64 MHz frequency. / 64 Kbytes of Flash program memory and 8 Kbytes of SRAM.  With 32pin LQFP 7x7x1.4 package; Manufacturer_Part_Number: STM32G0_LQFP32_T2; Vendor: STMicroelectronics
footprint LQFP-32
pins: 1 PB9 (io), 2 PC14-OSC32_IN (io), 3 PC15-OSC32_OUT (io), 4 VDD/VDDA (power), 5 VSS/VSSA (power), 6 NRST (io), 7 PA0 (io), 8 PA1 (io), 9 PA2 (io), 10 PA3 (io), 11 PA4 (io), 12 PA5 (io), 13 PA6 (io), 14 PA7 (io), 15 PB0 (io), 16 PB1 (io), 17 PB2 (io), 18 PA8 (io), 19 PA9 (io), 20 PC6 (io), 21 PA10 (io), 22 PA11 (io), 23 PA12 (io), 24 PA13 (io), 25 PA14-BOOT0 (io), 26 PA15 (io), 27 PB3 (io), 28 PB4 (io), 29 PB5 (io), 30 PB6 (io), 31 PB7 (io), 32 PB8 (io)

## STM32G041K8Ux
designator U?
The STM32G041x6/x8 mainstream microcontrollers are based on high-performance Arm® Cortex®-M0+ 32-bit RISC core operating at up to 64 MHz frequency. / 64 Kbytes of Flash program memory and 8 Kbytes of SRAM.  With 32pin UFQFPN  5x5x0.55  package; Manufacturer_Part_Number: stm32g0_ufqfpn32_t1; Built_By: EMA_Jessica; Vendor: STMicroelectronics
footprint UFQFPN-32
pins: 1 PB9 (io), 2 PC14-OSC32_IN (io), 3 PC15-OSC32_OUT (io), 4 VDD (power), 5 VSS (power), 6 PF2-NRST (io), 7 PA0 (io), 8 PA1 (io), 9 PA2 (io), 10 PA3 (io), 11 PA4 (io), 12 PA5 (io), 13 PA6 (io), 14 PA7 (io), 15 PB0 (io), 16 PB1 (io), 17 PB2 (io), 18 PA8 (io), 19 PA9 (io), 20 PC6 (io), 21 PA10 (io), 22 PA11[PA9] (io), 23 PA12[PA10] (io), 24 PA13 (io), 25 PA14-BOOT0 (io), 26 PA15 (io), 27 PB3 (io), 28 PB4 (io), 29 PB5 (io), 30 PB6 (io), 31 PB7 (io), 32 PB8 (io)

## STM32G070CBTx
designator U?
The STM32G070CB/KB/RB mainstream microcontrollers are based on high-performance Arm® Cortex®-M0+ 32-bit RISC core operating at up to 64 MHz frequency. / 128 Kbytes of Flash program memory and 36 Kbytes of SRAM. With 48pin LQFP 7x7x1.4 package; Manufacturer_Part_Number: stm32g0_lqfp48_t2; Vendor: STMicroelectronics
footprint LQFP48
pins: 1 PC13 (io), 2 PC14-OSC32_IN (io), 3 PC15-OSC32_OUT (io), 4 VBAT (power), 5 VREF+ (power), 6 VDD/VDDA (power), 7 VSS/VSSA (power), 8 PF0-OSC_IN (io), 9 PF1-OSC_OUT (io), 10 NRST (io), 11 PA0 (io), 12 PA1 (io), 13 PA2 (io), 14 PA3 (io), 15 PA4 (io), 16 PA5 (io), 17 PA6 (io), 18 PA7 (io), 19 PB0 (io), 20 PB1 (io), 21 PB2 (io), 22 PB10 (io), 23 PB11 (io), 24 PB12 (io), 25 PB13 (io), 26 PB14 (io), 27 PB15 (io), 28 PA8 (io), 29 PA9 (io), 30 PC6 (io), 31 PC7 (io), 32 PA10 (io), 33 PA11 (io), 34 PA12 (io), 35 PA13 (io), 36 PA14-BOOT0 (io), 37 PA15 (io), 38 PD0 (io), 39 PD1 (io), 40 PD2 (io), 41 PD3 (io), 42 PB3 (io), 43 PB4 (io), 44 PB5 (io), 45 PB6 (io), 46 PB7 (io), 47 PB8 (io), 48 PB9 (io)

## STM32G070KBTx
designator U?
The STM32G070CB/KB/RB mainstream microcontrollers are based on high-performance Arm® Cortex®-M0+ 32-bit RISC core operating at up to 64 MHz frequency. / 128 Kbytes of Flash program memory and 36 Kbytes of SRAM. With 32pin LQFP 7x7x1.4 package; Manufacturer_Part_Number: STM32G0_LQFP32_T2; Vendor: STMicroelectronics
footprint LQFP-32
pins: 1 PB9 (io), 2 PC14-OSC32_IN (io), 3 PC15-OSC32_OUT (io), 4 VDD/VDDA (power), 5 VSS/VSSA (power), 6 NRST (io), 7 PA0 (io), 8 PA1 (io), 9 PA2 (io), 10 PA3 (io), 11 PA4 (io), 12 PA5 (io), 13 PA6 (io), 14 PA7 (io), 15 PB0 (io), 16 PB1 (io), 17 PB2 (io), 18 PA8 (io), 19 PA9 (io), 20 PC6 (io), 21 PA10 (io), 22 PA11 (io), 23 PA12 (io), 24 PA13 (io), 25 PA14-BOOT0 (io), 26 PA15 (io), 27 PB3 (io), 28 PB4 (io), 29 PB5 (io), 30 PB6 (io), 31 PB7 (io), 32 PB8 (io)

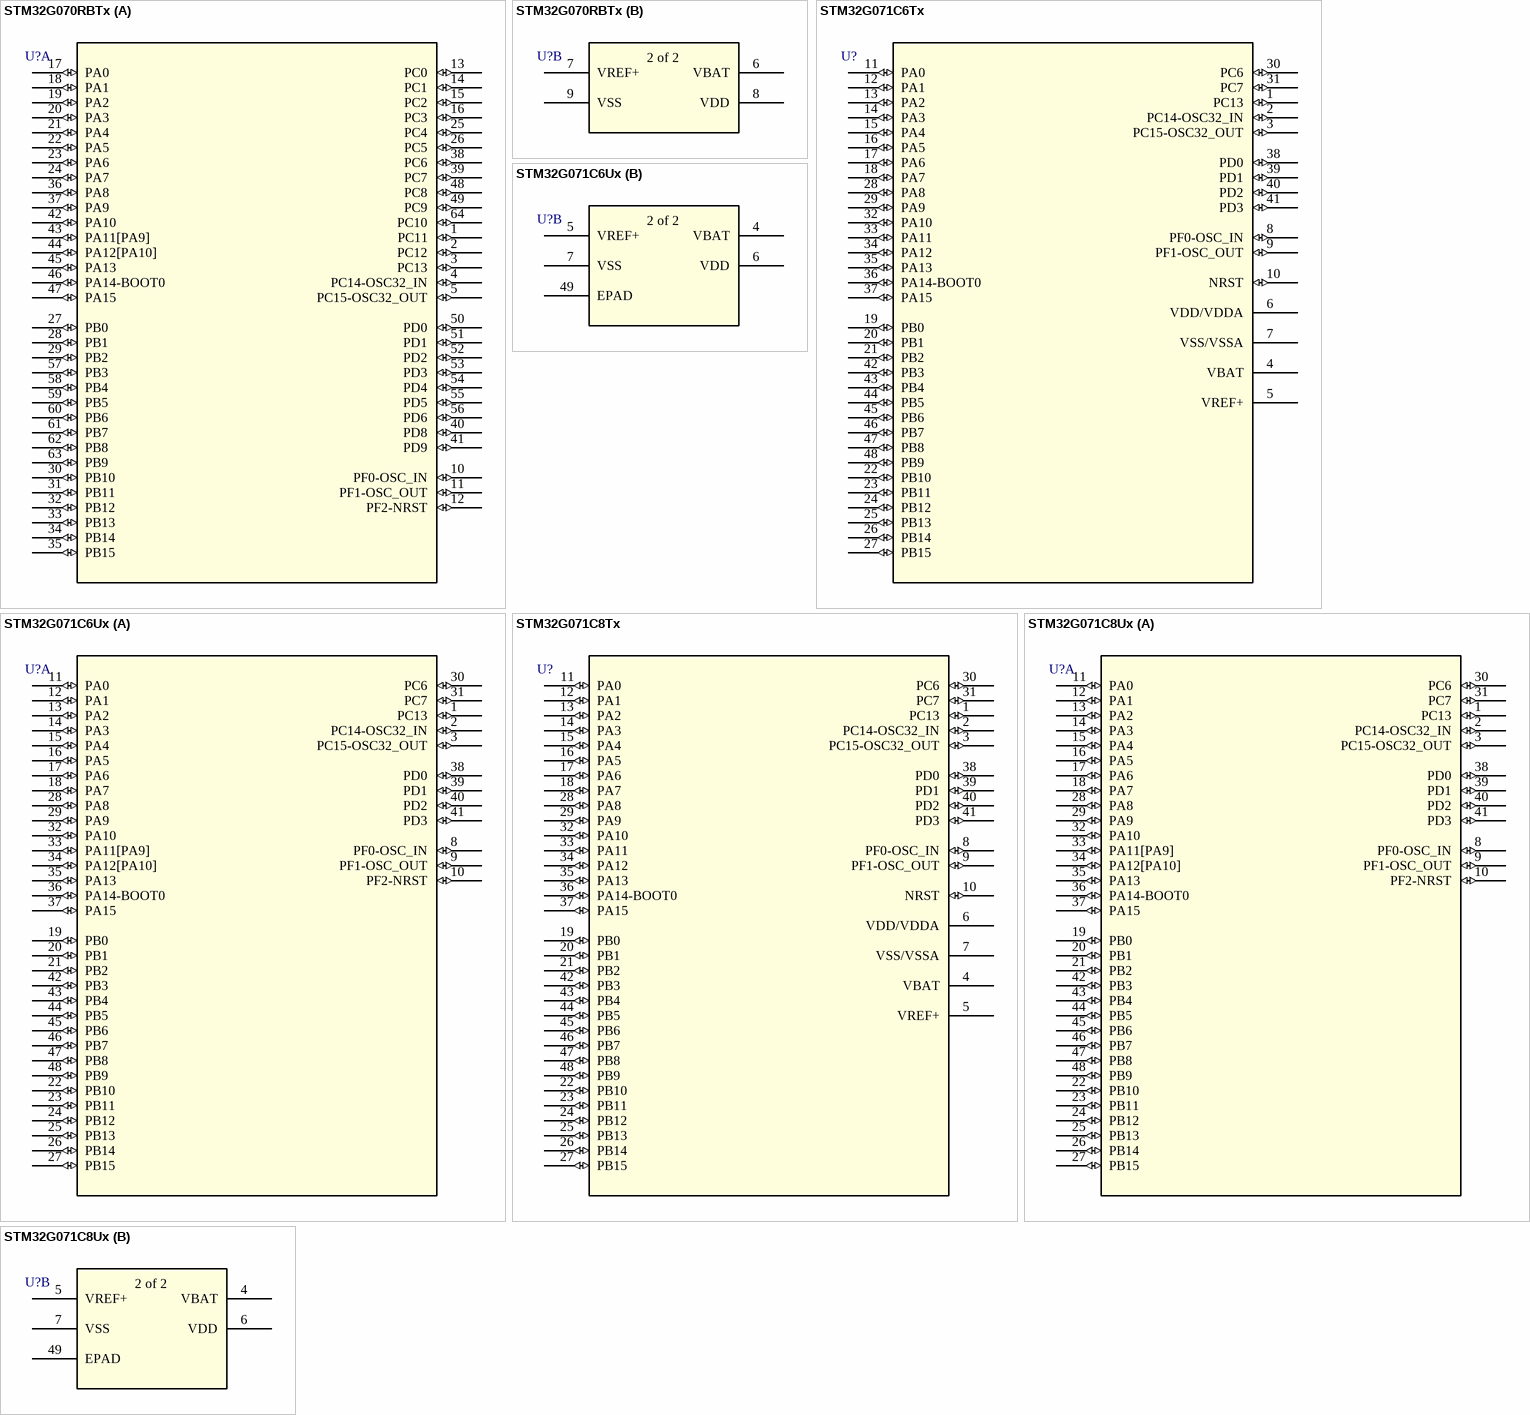
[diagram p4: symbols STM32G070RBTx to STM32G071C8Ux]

## STM32G070RBTx
designator U?
The STM32G070CB/KB/RB mainstream microcontrollers are based on high-performance Arm® Cortex®-M0+ 32-bit RISC core operating at up to 64 MHz frequency. / 128 Kbytes of Flash program memory and 36 Kbytes of SRAM. With 64pin LQFP 10x10x1.4 package; Manufacturer_Part_Number: stm32g0_lqfp64_t1; Built_By: EMA_Jessica; Vendor: STMicroelectronics
footprint LQFP-64
part A pins: 1 PC11 (io), 2 PC12 (io), 3 PC13 (io), 4 PC14-OSC32_IN (io), 5 PC15-OSC32_OUT (io), 10 PF0-OSC_IN (io), 11 PF1-OSC_OUT (io), 12 PF2-NRST (io), 13 PC0 (io), 14 PC1 (io), 15 PC2 (io), 16 PC3 (io), 17 PA0 (io), 18 PA1 (io), 19 PA2 (io), 20 PA3 (io), 21 PA4 (io), 22 PA5 (io), 23 PA6 (io), 24 PA7 (io), 25 PC4 (io), 26 PC5 (io), 27 PB0 (io), 28 PB1 (io), 29 PB2 (io), 30 PB10 (io), 31 PB11 (io), 32 PB12 (io), 33 PB13 (io), 34 PB14 (io), 35 PB15 (io), 36 PA8 (io), 37 PA9 (io), 38 PC6 (io), 39 PC7 (io), 40 PD8 (io), 41 PD9 (io), 42 PA10 (io), 43 PA11[PA9] (io), 44 PA12[PA10] (io), 45 PA13 (io), 46 PA14-BOOT0 (io), 47 PA15 (io), 48 PC8 (io), 49 PC9 (io), 50 PD0 (io), 51 PD1 (io), 52 PD2 (io), 53 PD3 (io), 54 PD4 (io), 55 PD5 (io), 56 PD6 (io), 57 PB3 (io), 58 PB4 (io), 59 PB5 (io), 60 PB6 (io), 61 PB7 (io), 62 PB8 (io), 63 PB9 (io), 64 PC10 (io)
part B pins: 6 VBAT (power), 7 VREF+ (power), 8 VDD (power), 9 VSS (power)

## STM32G071C6Tx
designator U?
The STM32G071x8/xB mainstream microcontrollers are based on high-performance Arm® Cortex®-M0+ 32-bit RISC core operating at up to 64 MHz frequency. / 32 Kbytes of Flash program memory and 8 Kbytes of SRAM. With 48pin LQFP 7x7x1.4 package; Manufacturer_Part_Number: stm32g0_lqfp48_t2; Vendor: STMicroelectronics
footprint LQFP48
pins: 1 PC13 (io), 2 PC14-OSC32_IN (io), 3 PC15-OSC32_OUT (io), 4 VBAT (power), 5 VREF+ (power), 6 VDD/VDDA (power), 7 VSS/VSSA (power), 8 PF0-OSC_IN (io), 9 PF1-OSC_OUT (io), 10 NRST (io), 11 PA0 (io), 12 PA1 (io), 13 PA2 (io), 14 PA3 (io), 15 PA4 (io), 16 PA5 (io), 17 PA6 (io), 18 PA7 (io), 19 PB0 (io), 20 PB1 (io), 21 PB2 (io), 22 PB10 (io), 23 PB11 (io), 24 PB12 (io), 25 PB13 (io), 26 PB14 (io), 27 PB15 (io), 28 PA8 (io), 29 PA9 (io), 30 PC6 (io), 31 PC7 (io), 32 PA10 (io), 33 PA11 (io), 34 PA12 (io), 35 PA13 (io), 36 PA14-BOOT0 (io), 37 PA15 (io), 38 PD0 (io), 39 PD1 (io), 40 PD2 (io), 41 PD3 (io), 42 PB3 (io), 43 PB4 (io), 44 PB5 (io), 45 PB6 (io), 46 PB7 (io), 47 PB8 (io), 48 PB9 (io)

## STM32G071C6Ux
designator U?
The STM32G071x8/xB mainstream microcontrollers are based on high-performance Arm® Cortex®-M0+ 32-bit RISC core operating at up to 64 MHz frequency. / 32 Kbytes of Flash program memory and 8 Kbytes of SRAM. With 48pin UFQFPN 7x7x0.55 package; Manufacturer_Part_Number: stm32g0_ufqfpn48_t1; Built_By: EMA_Jessica; Vendor: STMicroelectronics
footprint UFQFPN48-7x7mm
part A pins: 1 PC13 (io), 2 PC14-OSC32_IN (io), 3 PC15-OSC32_OUT (io), 8 PF0-OSC_IN (io), 9 PF1-OSC_OUT (io), 10 PF2-NRST (io), 11 PA0 (io), 12 PA1 (io), 13 PA2 (io), 14 PA3 (io), 15 PA4 (io), 16 PA5 (io), 17 PA6 (io), 18 PA7 (io), 19 PB0 (io), 20 PB1 (io), 21 PB2 (io), 22 PB10 (io), 23 PB11 (io), 24 PB12 (io), 25 PB13 (io), 26 PB14 (io), 27 PB15 (io), 28 PA8 (io), 29 PA9 (io), 30 PC6 (io), 31 PC7 (io), 32 PA10 (io), 33 PA11[PA9] (io), 34 PA12[PA10] (io), 35 PA13 (io), 36 PA14-BOOT0 (io), 37 PA15 (io), 38 PD0 (io), 39 PD1 (io), 40 PD2 (io), 41 PD3 (io), 42 PB3 (io), 43 PB4 (io), 44 PB5 (io), 45 PB6 (io), 46 PB7 (io), 47 PB8 (io), 48 PB9 (io)
part B pins: 4 VBAT (power), 5 VREF+ (power), 6 VDD (power), 7 VSS (power), 49 EPAD

## STM32G071C8Tx
designator U?
The STM32G071x8/xB mainstream microcontrollers are based on high-performance Arm® Cortex®-M0+ 32-bit RISC core operating at up to 64 MHz frequency. / 64 Kbytes of Flash program memory and 36 Kbytes of SRAM. With 48pin LQFP 7x7x1.4 package; Manufacturer_Part_Number: stm32g0_lqfp48_t2; Vendor: STMicroelectronics
footprint LQFP48
pins: 1 PC13 (io), 2 PC14-OSC32_IN (io), 3 PC15-OSC32_OUT (io), 4 VBAT (power), 5 VREF+ (power), 6 VDD/VDDA (power), 7 VSS/VSSA (power), 8 PF0-OSC_IN (io), 9 PF1-OSC_OUT (io), 10 NRST (io), 11 PA0 (io), 12 PA1 (io), 13 PA2 (io), 14 PA3 (io), 15 PA4 (io), 16 PA5 (io), 17 PA6 (io), 18 PA7 (io), 19 PB0 (io), 20 PB1 (io), 21 PB2 (io), 22 PB10 (io), 23 PB11 (io), 24 PB12 (io), 25 PB13 (io), 26 PB14 (io), 27 PB15 (io), 28 PA8 (io), 29 PA9 (io), 30 PC6 (io), 31 PC7 (io), 32 PA10 (io), 33 PA11 (io), 34 PA12 (io), 35 PA13 (io), 36 PA14-BOOT0 (io), 37 PA15 (io), 38 PD0 (io), 39 PD1 (io), 40 PD2 (io), 41 PD3 (io), 42 PB3 (io), 43 PB4 (io), 44 PB5 (io), 45 PB6 (io), 46 PB7 (io), 47 PB8 (io), 48 PB9 (io)

## STM32G071C8Ux
designator U?
The STM32G071x8/xB mainstream microcontrollers are based on high-performance Arm® Cortex®-M0+ 32-bit RISC core operating at up to 64 MHz frequency. / 64 Kbytes of Flash program memory and 36 Kbytes of SRAM. With 48pin UFQFPN 7x7x0.55 package; Manufacturer_Part_Number: stm32g0_ufqfpn48_t1; Built_By: EMA_Jessica; Vendor: STMicroelectronics
footprint UFQFPN48-7x7mm
part A pins: 1 PC13 (io), 2 PC14-OSC32_IN (io), 3 PC15-OSC32_OUT (io), 8 PF0-OSC_IN (io), 9 PF1-OSC_OUT (io), 10 PF2-NRST (io), 11 PA0 (io), 12 PA1 (io), 13 PA2 (io), 14 PA3 (io), 15 PA4 (io), 16 PA5 (io), 17 PA6 (io), 18 PA7 (io), 19 PB0 (io), 20 PB1 (io), 21 PB2 (io), 22 PB10 (io), 23 PB11 (io), 24 PB12 (io), 25 PB13 (io), 26 PB14 (io), 27 PB15 (io), 28 PA8 (io), 29 PA9 (io), 30 PC6 (io), 31 PC7 (io), 32 PA10 (io), 33 PA11[PA9] (io), 34 PA12[PA10] (io), 35 PA13 (io), 36 PA14-BOOT0 (io), 37 PA15 (io), 38 PD0 (io), 39 PD1 (io), 40 PD2 (io), 41 PD3 (io), 42 PB3 (io), 43 PB4 (io), 44 PB5 (io), 45 PB6 (io), 46 PB7 (io), 47 PB8 (io), 48 PB9 (io)
part B pins: 4 VBAT (power), 5 VREF+ (power), 6 VDD (power), 7 VSS (power), 49 EPAD

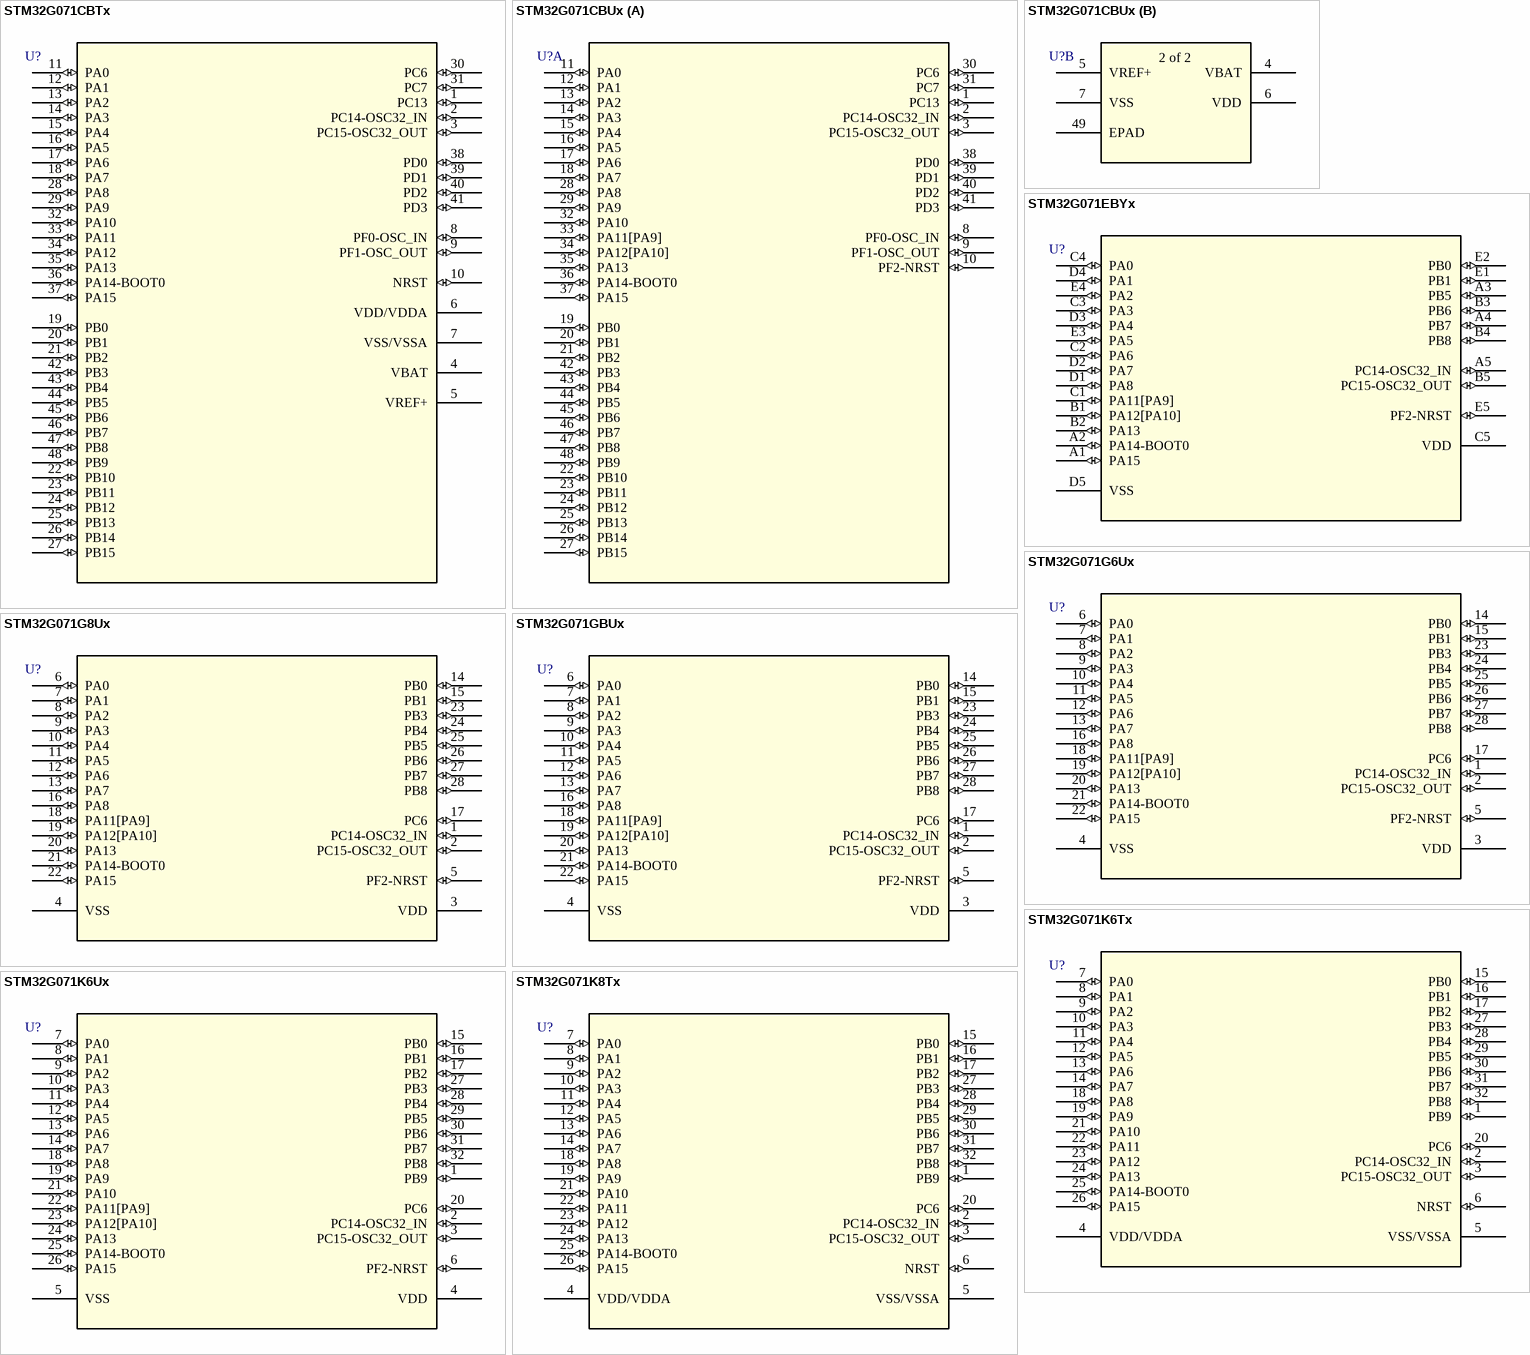
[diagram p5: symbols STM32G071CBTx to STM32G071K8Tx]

## STM32G071CBTx
designator U?
The STM32G071x8/xB mainstream microcontrollers are based on high-performance Arm® Cortex®-M0+ 32-bit RISC core operating at up to 64 MHz frequency. / 128 Kbytes of Flash program memory and 36 Kbytes of SRAM. With 48pin LQFP 7x7x1.4 package; Manufacturer_Part_Number: stm32g0_lqfp48_t2; Vendor: STMicroelectronics
footprint LQFP48
pins: 1 PC13 (io), 2 PC14-OSC32_IN (io), 3 PC15-OSC32_OUT (io), 4 VBAT (power), 5 VREF+ (power), 6 VDD/VDDA (power), 7 VSS/VSSA (power), 8 PF0-OSC_IN (io), 9 PF1-OSC_OUT (io), 10 NRST (io), 11 PA0 (io), 12 PA1 (io), 13 PA2 (io), 14 PA3 (io), 15 PA4 (io), 16 PA5 (io), 17 PA6 (io), 18 PA7 (io), 19 PB0 (io), 20 PB1 (io), 21 PB2 (io), 22 PB10 (io), 23 PB11 (io), 24 PB12 (io), 25 PB13 (io), 26 PB14 (io), 27 PB15 (io), 28 PA8 (io), 29 PA9 (io), 30 PC6 (io), 31 PC7 (io), 32 PA10 (io), 33 PA11 (io), 34 PA12 (io), 35 PA13 (io), 36 PA14-BOOT0 (io), 37 PA15 (io), 38 PD0 (io), 39 PD1 (io), 40 PD2 (io), 41 PD3 (io), 42 PB3 (io), 43 PB4 (io), 44 PB5 (io), 45 PB6 (io), 46 PB7 (io), 47 PB8 (io), 48 PB9 (io)

## STM32G071CBUx
designator U?
The STM32G071x8/xB mainstream microcontrollers are based on high-performance Arm® Cortex®-M0+ 32-bit RISC core operating at up to 64 MHz frequency. / 128 Kbytes of Flash program memory and 36 Kbytes of SRAM. With 48pin UFQFPN 7x7x0.55 package; Manufacturer_Part_Number: stm32g0_ufqfpn48_t1; Built_By: EMA_Jessica; Vendor: STMicroelectronics
footprint UFQFPN48-7x7mm
part A pins: 1 PC13 (io), 2 PC14-OSC32_IN (io), 3 PC15-OSC32_OUT (io), 8 PF0-OSC_IN (io), 9 PF1-OSC_OUT (io), 10 PF2-NRST (io), 11 PA0 (io), 12 PA1 (io), 13 PA2 (io), 14 PA3 (io), 15 PA4 (io), 16 PA5 (io), 17 PA6 (io), 18 PA7 (io), 19 PB0 (io), 20 PB1 (io), 21 PB2 (io), 22 PB10 (io), 23 PB11 (io), 24 PB12 (io), 25 PB13 (io), 26 PB14 (io), 27 PB15 (io), 28 PA8 (io), 29 PA9 (io), 30 PC6 (io), 31 PC7 (io), 32 PA10 (io), 33 PA11[PA9] (io), 34 PA12[PA10] (io), 35 PA13 (io), 36 PA14-BOOT0 (io), 37 PA15 (io), 38 PD0 (io), 39 PD1 (io), 40 PD2 (io), 41 PD3 (io), 42 PB3 (io), 43 PB4 (io), 44 PB5 (io), 45 PB6 (io), 46 PB7 (io), 47 PB8 (io), 48 PB9 (io)
part B pins: 4 VBAT (power), 5 VREF+ (power), 6 VDD (power), 7 VSS (power), 49 EPAD

## STM32G071EBYx
designator U?
The STM32G071x8/xB mainstream microcontrollers are based on high-performance Arm® Cortex®-M0+ 32-bit RISC core operating at up to 64 MHz frequency. / 128 Kbytes of Flash program memory and 36 Kbytes of SRAM. With 25pin WLCSP  2.3x2.5 package; Manufacturer_Part_Number: stm32g0_wlcsp25_t1; Built_By: EMA_Jessica; Vendor: STMicroelectronics
footprint WLCSP25
pins: A1 PA15 (io), A2 PA14-BOOT0 (io), A3 PB5 (io), A4 PB7 (io), A5 PC14-OSC32_IN (io), B1 PA12[PA10] (io), B2 PA13 (io), B3 PB6 (io), B4 PB8 (io), B5 PC15-OSC32_OUT (io), C1 PA11[PA9] (io), C2 PA6 (io), C3 PA3 (io), C4 PA0 (io), C5 VDD (power), D1 PA8 (io), D2 PA7 (io), D3 PA4 (io), D4 PA1 (io), D5 VSS (power), E1 PB1 (io), E2 PB0 (io), E3 PA5 (io), E4 PA2 (io), E5 PF2-NRST (io)

## STM32G071G6Ux
designator U?
The STM32G071x8/xB mainstream microcontrollers are based on high-performance Arm® Cortex®-M0+ 32-bit RISC core operating at up to 64 MHz frequency. / 32 Kbytes of Flash program memory and 8 Kbytes of SRAM. With 28pin UFQFPN 4x4x0.55 package; Manufacturer_Part_Number: stm32g0_ufqfpn28_t1; Built_By: EMA_Jessica; Vendor: STMicroelectronics
footprint UFQFPN-28
pins: 1 PC14-OSC32_IN (io), 2 PC15-OSC32_OUT (io), 3 VDD (power), 4 VSS (power), 5 PF2-NRST (io), 6 PA0 (io), 7 PA1 (io), 8 PA2 (io), 9 PA3 (io), 10 PA4 (io), 11 PA5 (io), 12 PA6 (io), 13 PA7 (io), 14 PB0 (io), 15 PB1 (io), 16 PA8 (io), 17 PC6 (io), 18 PA11[PA9] (io), 19 PA12[PA10] (io), 20 PA13 (io), 21 PA14-BOOT0 (io), 22 PA15 (io), 23 PB3 (io), 24 PB4 (io), 25 PB5 (io), 26 PB6 (io), 27 PB7 (io), 28 PB8 (io)

## STM32G071G8Ux
designator U?
The STM32G071x8/xB mainstream microcontrollers are based on high-performance Arm® Cortex®-M0+ 32-bit RISC core operating at up to 64 MHz frequency. / 64 Kbytes of Flash program memory and 36 Kbytes of SRAM. With 28pin UFQFPN 4x4x0.55 package; Manufacturer_Part_Number: stm32g0_ufqfpn28_t1; Built_By: EMA_Jessica; Vendor: STMicroelectronics
footprint UFQFPN-28
pins: 1 PC14-OSC32_IN (io), 2 PC15-OSC32_OUT (io), 3 VDD (power), 4 VSS (power), 5 PF2-NRST (io), 6 PA0 (io), 7 PA1 (io), 8 PA2 (io), 9 PA3 (io), 10 PA4 (io), 11 PA5 (io), 12 PA6 (io), 13 PA7 (io), 14 PB0 (io), 15 PB1 (io), 16 PA8 (io), 17 PC6 (io), 18 PA11[PA9] (io), 19 PA12[PA10] (io), 20 PA13 (io), 21 PA14-BOOT0 (io), 22 PA15 (io), 23 PB3 (io), 24 PB4 (io), 25 PB5 (io), 26 PB6 (io), 27 PB7 (io), 28 PB8 (io)

## STM32G071GBUx
designator U?
The STM32G071x8/xB mainstream microcontrollers are based on high-performance Arm® Cortex®-M0+ 32-bit RISC core operating at up to 64 MHz frequency. / 128 Kbytes of Flash program memory and 36 Kbytes of SRAM. With 28pin UFQFPN 4x4x0.55 package; Manufacturer_Part_Number: stm32g0_ufqfpn28_t1; Built_By: EMA_Jessica; Vendor: STMicroelectronics
footprint UFQFPN-28
pins: 1 PC14-OSC32_IN (io), 2 PC15-OSC32_OUT (io), 3 VDD (power), 4 VSS (power), 5 PF2-NRST (io), 6 PA0 (io), 7 PA1 (io), 8 PA2 (io), 9 PA3 (io), 10 PA4 (io), 11 PA5 (io), 12 PA6 (io), 13 PA7 (io), 14 PB0 (io), 15 PB1 (io), 16 PA8 (io), 17 PC6 (io), 18 PA11[PA9] (io), 19 PA12[PA10] (io), 20 PA13 (io), 21 PA14-BOOT0 (io), 22 PA15 (io), 23 PB3 (io), 24 PB4 (io), 25 PB5 (io), 26 PB6 (io), 27 PB7 (io), 28 PB8 (io)

## STM32G071K6Tx
designator U?
The STM32G071x8/xB mainstream microcontrollers are based on high-performance Arm® Cortex®-M0+ 32-bit RISC core operating at up to 64 MHz frequency. / 32 Kbytes of Flash program memory and 8 Kbytes of SRAM. With 32pin LQFP 7x7x1.4 package; Manufacturer_Part_Number: STM32G0_LQFP32_T2; Vendor: STMicroelectronics
footprint LQFP-32
pins: 1 PB9 (io), 2 PC14-OSC32_IN (io), 3 PC15-OSC32_OUT (io), 4 VDD/VDDA (power), 5 VSS/VSSA (power), 6 NRST (io), 7 PA0 (io), 8 PA1 (io), 9 PA2 (io), 10 PA3 (io), 11 PA4 (io), 12 PA5 (io), 13 PA6 (io), 14 PA7 (io), 15 PB0 (io), 16 PB1 (io), 17 PB2 (io), 18 PA8 (io), 19 PA9 (io), 20 PC6 (io), 21 PA10 (io), 22 PA11 (io), 23 PA12 (io), 24 PA13 (io), 25 PA14-BOOT0 (io), 26 PA15 (io), 27 PB3 (io), 28 PB4 (io), 29 PB5 (io), 30 PB6 (io), 31 PB7 (io), 32 PB8 (io)

## STM32G071K6Ux
designator U?
The STM32G071x8/xB mainstream microcontrollers are based on high-performance Arm® Cortex®-M0+ 32-bit RISC core operating at up to 64 MHz frequency. / 32 Kbytes of Flash program memory and 8 Kbytes of SRAM. With 32pin UFQFPN  5x5x0.55  package; Manufacturer_Part_Number: stm32g0_ufqfpn32_t1; Built_By: EMA_Jessica; Vendor: STMicroelectronics
footprint UFQFPN-32
pins: 1 PB9 (io), 2 PC14-OSC32_IN (io), 3 PC15-OSC32_OUT (io), 4 VDD (power), 5 VSS (power), 6 PF2-NRST (io), 7 PA0 (io), 8 PA1 (io), 9 PA2 (io), 10 PA3 (io), 11 PA4 (io), 12 PA5 (io), 13 PA6 (io), 14 PA7 (io), 15 PB0 (io), 16 PB1 (io), 17 PB2 (io), 18 PA8 (io), 19 PA9 (io), 20 PC6 (io), 21 PA10 (io), 22 PA11[PA9] (io), 23 PA12[PA10] (io), 24 PA13 (io), 25 PA14-BOOT0 (io), 26 PA15 (io), 27 PB3 (io), 28 PB4 (io), 29 PB5 (io), 30 PB6 (io), 31 PB7 (io), 32 PB8 (io)

## STM32G071K8Tx
designator U?
The STM32G071x8/xB mainstream microcontrollers are based on high-performance Arm® Cortex®-M0+ 32-bit RISC core operating at up to 64 MHz frequency. / 64 Kbytes of Flash program memory and 36 Kbytes of SRAM. With 32pin LQFP 7x7x1.4 package; Manufacturer_Part_Number: STM32G0_LQFP32_T2; Vendor: STMicroelectronics
footprint LQFP-32
pins: 1 PB9 (io), 2 PC14-OSC32_IN (io), 3 PC15-OSC32_OUT (io), 4 VDD/VDDA (power), 5 VSS/VSSA (power), 6 NRST (io), 7 PA0 (io), 8 PA1 (io), 9 PA2 (io), 10 PA3 (io), 11 PA4 (io), 12 PA5 (io), 13 PA6 (io), 14 PA7 (io), 15 PB0 (io), 16 PB1 (io), 17 PB2 (io), 18 PA8 (io), 19 PA9 (io), 20 PC6 (io), 21 PA10 (io), 22 PA11 (io), 23 PA12 (io), 24 PA13 (io), 25 PA14-BOOT0 (io), 26 PA15 (io), 27 PB3 (io), 28 PB4 (io), 29 PB5 (io), 30 PB6 (io), 31 PB7 (io), 32 PB8 (io)

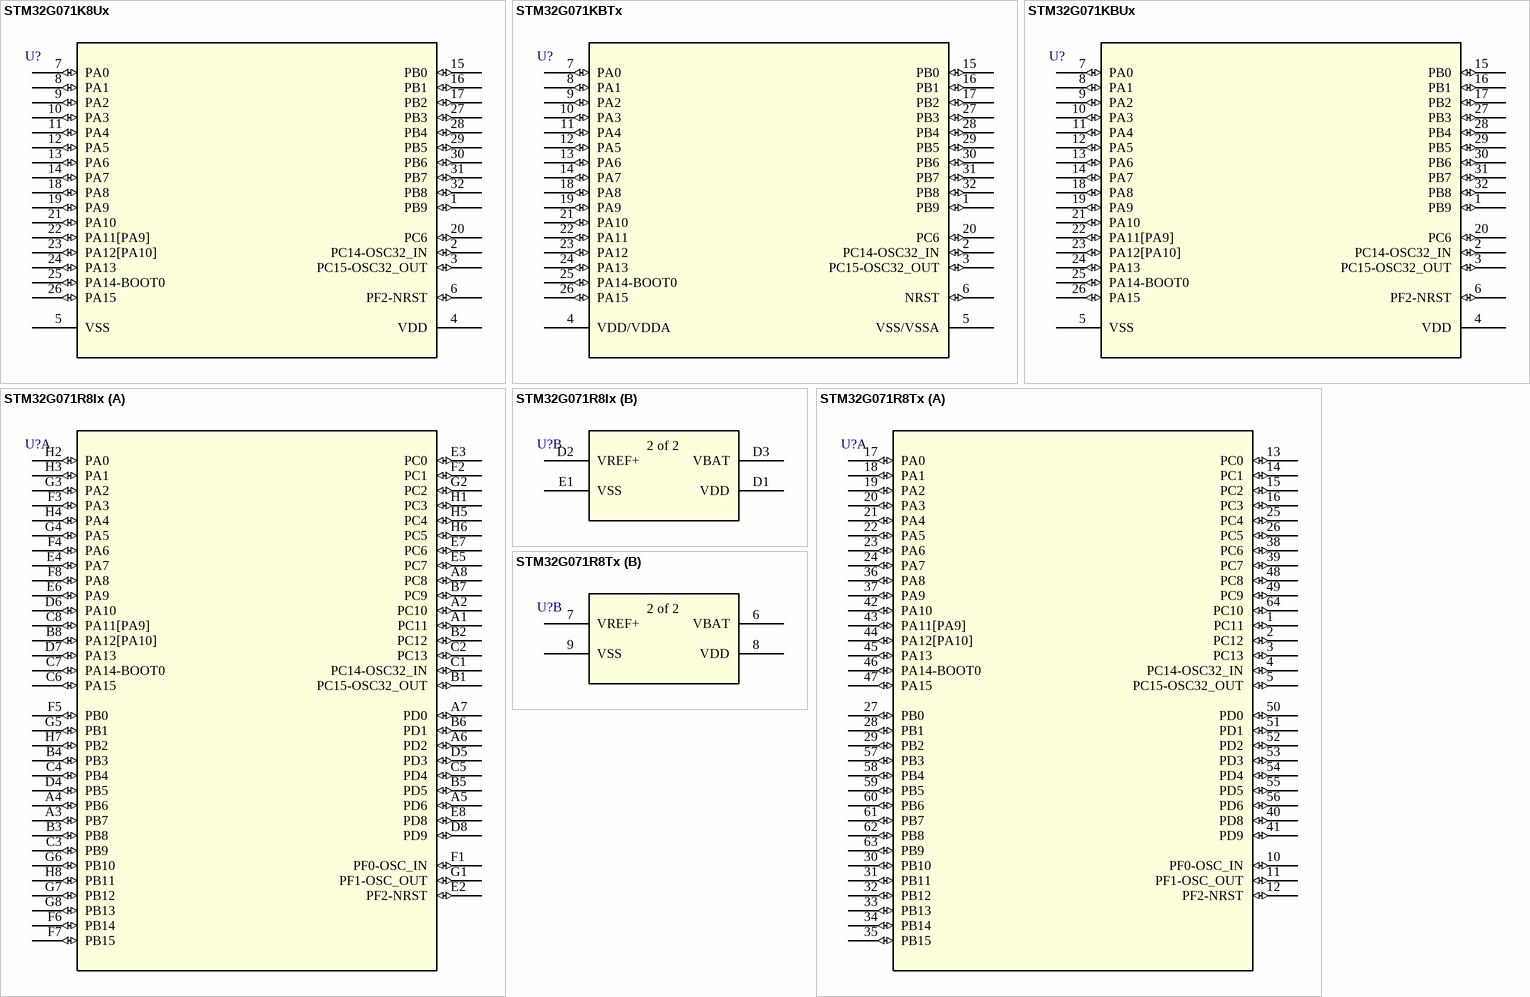
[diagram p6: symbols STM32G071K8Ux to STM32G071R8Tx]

## STM32G071K8Ux
designator U?
The STM32G071x8/xB mainstream microcontrollers are based on high-performance Arm® Cortex®-M0+ 32-bit RISC core operating at up to 64 MHz frequency. / 64 Kbytes of Flash program memory and 36 Kbytes of SRAM. With 32pin UFQFPN  5x5x0.55  package; Manufacturer_Part_Number: stm32g0_ufqfpn32_t1; Built_By: EMA_Jessica; Vendor: STMicroelectronics
footprint UFQFPN-32
pins: 1 PB9 (io), 2 PC14-OSC32_IN (io), 3 PC15-OSC32_OUT (io), 4 VDD (power), 5 VSS (power), 6 PF2-NRST (io), 7 PA0 (io), 8 PA1 (io), 9 PA2 (io), 10 PA3 (io), 11 PA4 (io), 12 PA5 (io), 13 PA6 (io), 14 PA7 (io), 15 PB0 (io), 16 PB1 (io), 17 PB2 (io), 18 PA8 (io), 19 PA9 (io), 20 PC6 (io), 21 PA10 (io), 22 PA11[PA9] (io), 23 PA12[PA10] (io), 24 PA13 (io), 25 PA14-BOOT0 (io), 26 PA15 (io), 27 PB3 (io), 28 PB4 (io), 29 PB5 (io), 30 PB6 (io), 31 PB7 (io), 32 PB8 (io)

## STM32G071KBTx
designator U?
The STM32G071x8/xB mainstream microcontrollers are based on high-performance Arm® Cortex®-M0+ 32-bit RISC core operating at up to 64 MHz frequency. / 128 Kbytes of Flash program memory and 36 Kbytes of SRAM. With 32pin LQFP 7x7x1.4 package; Manufacturer_Part_Number: STM32G0_LQFP32_T2; Vendor: STMicroelectronics
footprint LQFP-32
pins: 1 PB9 (io), 2 PC14-OSC32_IN (io), 3 PC15-OSC32_OUT (io), 4 VDD/VDDA (power), 5 VSS/VSSA (power), 6 NRST (io), 7 PA0 (io), 8 PA1 (io), 9 PA2 (io), 10 PA3 (io), 11 PA4 (io), 12 PA5 (io), 13 PA6 (io), 14 PA7 (io), 15 PB0 (io), 16 PB1 (io), 17 PB2 (io), 18 PA8 (io), 19 PA9 (io), 20 PC6 (io), 21 PA10 (io), 22 PA11 (io), 23 PA12 (io), 24 PA13 (io), 25 PA14-BOOT0 (io), 26 PA15 (io), 27 PB3 (io), 28 PB4 (io), 29 PB5 (io), 30 PB6 (io), 31 PB7 (io), 32 PB8 (io)

## STM32G071KBUx
designator U?
The STM32G071x8/xB mainstream microcontrollers are based on high-performance Arm® Cortex®-M0+ 32-bit RISC core operating at up to 64 MHz frequency. / 128 Kbytes of Flash program memory and 36 Kbytes of SRAM. With 32pin UFQFPN  5x5x0.55  package; Manufacturer_Part_Number: stm32g0_ufqfpn32_t1; Built_By: EMA_Jessica; Vendor: STMicroelectronics
footprint UFQFPN-32
pins: 1 PB9 (io), 2 PC14-OSC32_IN (io), 3 PC15-OSC32_OUT (io), 4 VDD (power), 5 VSS (power), 6 PF2-NRST (io), 7 PA0 (io), 8 PA1 (io), 9 PA2 (io), 10 PA3 (io), 11 PA4 (io), 12 PA5 (io), 13 PA6 (io), 14 PA7 (io), 15 PB0 (io), 16 PB1 (io), 17 PB2 (io), 18 PA8 (io), 19 PA9 (io), 20 PC6 (io), 21 PA10 (io), 22 PA11[PA9] (io), 23 PA12[PA10] (io), 24 PA13 (io), 25 PA14-BOOT0 (io), 26 PA15 (io), 27 PB3 (io), 28 PB4 (io), 29 PB5 (io), 30 PB6 (io), 31 PB7 (io), 32 PB8 (io)

## STM32G071R8Ix
designator U?
The STM32G071x8/xB mainstream microcontrollers are based on high-performance Arm® Cortex®-M0+ 32-bit RISC core operating at up to 64 MHz frequency. / 64 Kbytes of Flash program memory and 36 Kbytes of SRAM. With 64pin UFBGA 5x5x0.5 package /; Manufacturer_Part_Number: stm32g0_ufbga64_t1; Built_By: EMA_Jessica; Vendor: STMicroelectronics
footprint UFBGA64-5x5mm
part A pins: A1 PC11 (io), A2 PC10 (io), A3 PB7 (io), A4 PB6 (io), A5 PD6 (io), A6 PD2 (io), A7 PD0 (io), A8 PC8 (io), B1 PC15-OSC32_OUT (io), B2 PC12 (io), B3 PB8 (io), B4 PB3 (io), B5 PD5 (io), B6 PD1 (io), B7 PC9 (io), B8 PA12[PA10] (io), C1 PC14-OSC32_IN (io), C2 PC13 (io), C3 PB9 (io), C4 PB4 (io), C5 PD4 (io), C6 PA15 (io), C7 PA14-BOOT0 (io), C8 PA11[PA9] (io), D4 PB5 (io), D5 PD3 (io), D6 PA10 (io), D7 PA13 (io), D8 PD9 (io), E2 PF2-NRST (io), E3 PC0 (io), E4 PA7 (io), E5 PC7 (io), E6 PA9 (io), E7 PC6 (io), E8 PD8 (io), F1 PF0-OSC_IN (io), F2 PC1 (io), F3 PA3 (io), F4 PA6 (io), F5 PB0 (io), F6 PB14 (io), F7 PB15 (io), F8 PA8 (io), G1 PF1-OSC_OUT (io), G2 PC2 (io), G3 PA2 (io), G4 PA5 (io), G5 PB1 (io), G6 PB10 (io), G7 PB12 (io), G8 PB13 (io), H1 PC3 (io), H2 PA0 (io), H3 PA1 (io), H4 PA4 (io), H5 PC4 (io), H6 PC5 (io), H7 PB2 (io), H8 PB11 (io)
part B pins: D1 VDD (power), D2 VREF+ (power), D3 VBAT (power), E1 VSS (power)

## STM32G071R8Tx
designator U?
The STM32G071x8/xB mainstream microcontrollers are based on high-performance Arm® Cortex®-M0+ 32-bit RISC core operating at up to 64 MHz frequency. / 64 Kbytes of Flash program memory and 36 Kbytes of SRAM. With 64pin LQFP 10x10x1.4 package; Manufacturer_Part_Number: stm32g0_lqfp64_t1; Built_By: EMA_Jessica; Vendor: STMicroelectronics
footprint LQFP-64
part A pins: 1 PC11 (io), 2 PC12 (io), 3 PC13 (io), 4 PC14-OSC32_IN (io), 5 PC15-OSC32_OUT (io), 10 PF0-OSC_IN (io), 11 PF1-OSC_OUT (io), 12 PF2-NRST (io), 13 PC0 (io), 14 PC1 (io), 15 PC2 (io), 16 PC3 (io), 17 PA0 (io), 18 PA1 (io), 19 PA2 (io), 20 PA3 (io), 21 PA4 (io), 22 PA5 (io), 23 PA6 (io), 24 PA7 (io), 25 PC4 (io), 26 PC5 (io), 27 PB0 (io), 28 PB1 (io), 29 PB2 (io), 30 PB10 (io), 31 PB11 (io), 32 PB12 (io), 33 PB13 (io), 34 PB14 (io), 35 PB15 (io), 36 PA8 (io), 37 PA9 (io), 38 PC6 (io), 39 PC7 (io), 40 PD8 (io), 41 PD9 (io), 42 PA10 (io), 43 PA11[PA9] (io), 44 PA12[PA10] (io), 45 PA13 (io), 46 PA14-BOOT0 (io), 47 PA15 (io), 48 PC8 (io), 49 PC9 (io), 50 PD0 (io), 51 PD1 (io), 52 PD2 (io), 53 PD3 (io), 54 PD4 (io), 55 PD5 (io), 56 PD6 (io), 57 PB3 (io), 58 PB4 (io), 59 PB5 (io), 60 PB6 (io), 61 PB7 (io), 62 PB8 (io), 63 PB9 (io), 64 PC10 (io)
part B pins: 6 VBAT (power), 7 VREF+ (power), 8 VDD (power), 9 VSS (power)

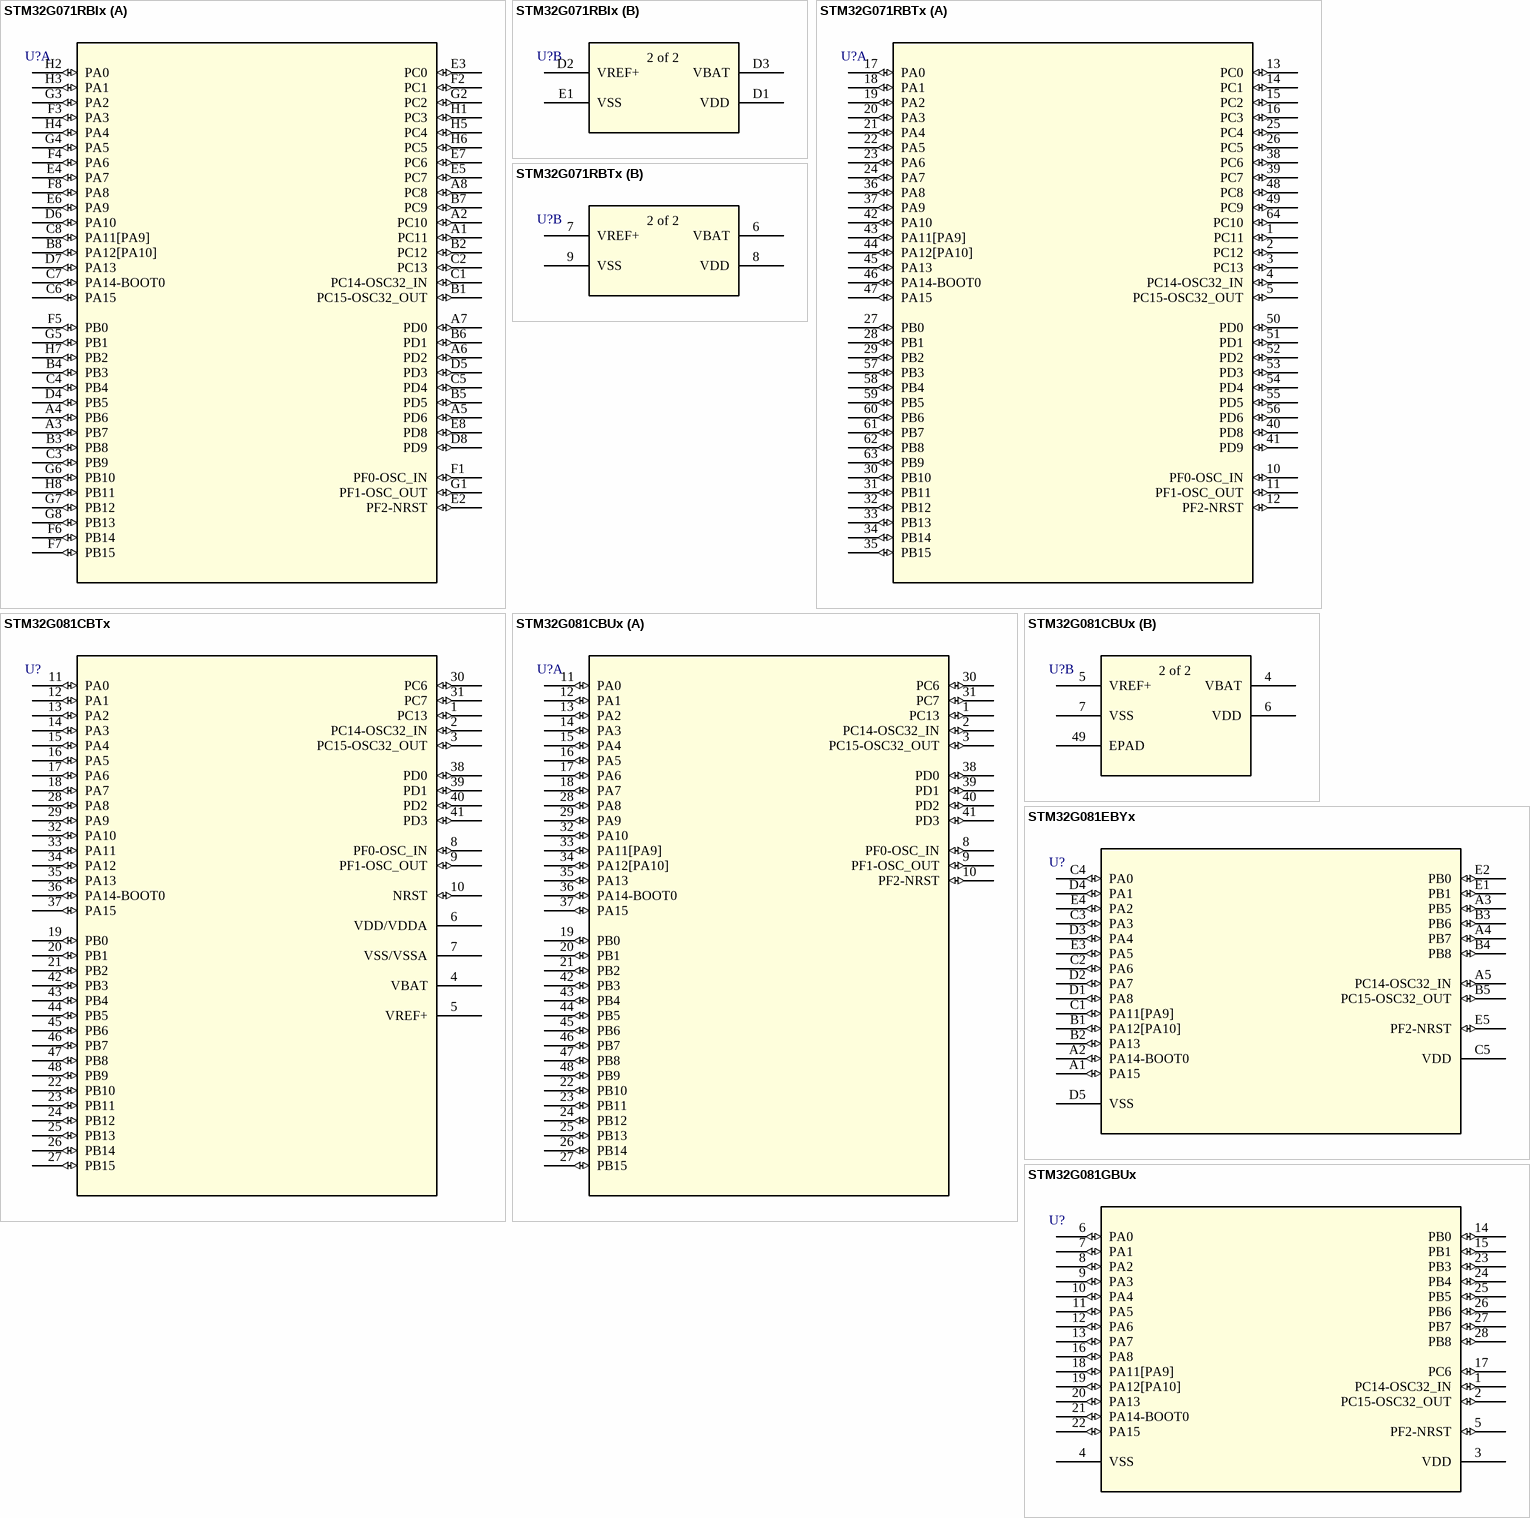
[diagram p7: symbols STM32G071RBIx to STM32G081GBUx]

## STM32G071RBIx
designator U?
The STM32G071x8/xB mainstream microcontrollers are based on high-performance Arm® Cortex®-M0+ 32-bit RISC core operating at up to 64 MHz frequency. / 128 Kbytes of Flash program memory and 36 Kbytes of SRAM. With 64pin UFBGA 5x5x0.5 package; Manufacturer_Part_Number: stm32g0_ufbga64_t1; Built_By: EMA_Jessica; Vendor: STMicroelectronics
footprint UFBGA64-5x5mm
part A pins: A1 PC11 (io), A2 PC10 (io), A3 PB7 (io), A4 PB6 (io), A5 PD6 (io), A6 PD2 (io), A7 PD0 (io), A8 PC8 (io), B1 PC15-OSC32_OUT (io), B2 PC12 (io), B3 PB8 (io), B4 PB3 (io), B5 PD5 (io), B6 PD1 (io), B7 PC9 (io), B8 PA12[PA10] (io), C1 PC14-OSC32_IN (io), C2 PC13 (io), C3 PB9 (io), C4 PB4 (io), C5 PD4 (io), C6 PA15 (io), C7 PA14-BOOT0 (io), C8 PA11[PA9] (io), D4 PB5 (io), D5 PD3 (io), D6 PA10 (io), D7 PA13 (io), D8 PD9 (io), E2 PF2-NRST (io), E3 PC0 (io), E4 PA7 (io), E5 PC7 (io), E6 PA9 (io), E7 PC6 (io), E8 PD8 (io), F1 PF0-OSC_IN (io), F2 PC1 (io), F3 PA3 (io), F4 PA6 (io), F5 PB0 (io), F6 PB14 (io), F7 PB15 (io), F8 PA8 (io), G1 PF1-OSC_OUT (io), G2 PC2 (io), G3 PA2 (io), G4 PA5 (io), G5 PB1 (io), G6 PB10 (io), G7 PB12 (io), G8 PB13 (io), H1 PC3 (io), H2 PA0 (io), H3 PA1 (io), H4 PA4 (io), H5 PC4 (io), H6 PC5 (io), H7 PB2 (io), H8 PB11 (io)
part B pins: D1 VDD (power), D2 VREF+ (power), D3 VBAT (power), E1 VSS (power)

## STM32G071RBTx
designator U?
The STM32G071x8/xB mainstream microcontrollers are based on high-performance Arm® Cortex®-M0+ 32-bit RISC core operating at up to 64 MHz frequency. / 128 Kbytes of Flash program memory and 36 Kbytes of SRAM. With 64pin LQFP 10x10x1.4 package; Manufacturer_Part_Number: stm32g0_lqfp64_t1; Built_By: EMA_Jessica; Vendor: STMicroelectronics
footprint LQFP-64
part A pins: 1 PC11 (io), 2 PC12 (io), 3 PC13 (io), 4 PC14-OSC32_IN (io), 5 PC15-OSC32_OUT (io), 10 PF0-OSC_IN (io), 11 PF1-OSC_OUT (io), 12 PF2-NRST (io), 13 PC0 (io), 14 PC1 (io), 15 PC2 (io), 16 PC3 (io), 17 PA0 (io), 18 PA1 (io), 19 PA2 (io), 20 PA3 (io), 21 PA4 (io), 22 PA5 (io), 23 PA6 (io), 24 PA7 (io), 25 PC4 (io), 26 PC5 (io), 27 PB0 (io), 28 PB1 (io), 29 PB2 (io), 30 PB10 (io), 31 PB11 (io), 32 PB12 (io), 33 PB13 (io), 34 PB14 (io), 35 PB15 (io), 36 PA8 (io), 37 PA9 (io), 38 PC6 (io), 39 PC7 (io), 40 PD8 (io), 41 PD9 (io), 42 PA10 (io), 43 PA11[PA9] (io), 44 PA12[PA10] (io), 45 PA13 (io), 46 PA14-BOOT0 (io), 47 PA15 (io), 48 PC8 (io), 49 PC9 (io), 50 PD0 (io), 51 PD1 (io), 52 PD2 (io), 53 PD3 (io), 54 PD4 (io), 55 PD5 (io), 56 PD6 (io), 57 PB3 (io), 58 PB4 (io), 59 PB5 (io), 60 PB6 (io), 61 PB7 (io), 62 PB8 (io), 63 PB9 (io), 64 PC10 (io)
part B pins: 6 VBAT (power), 7 VREF+ (power), 8 VDD (power), 9 VSS (power)

## STM32G081CBTx
designator U?
The STM32G081xB mainstream microcontrollers are based on high-performance Arm® Cortex®-M0+ 32-bit RISC core operating at up to 64 MHz frequency. / 128 Kbytes of Flash program memory and 36 Kbytes of SRAM. With 48pin LQFP 7x7x1.4 package; Manufacturer_Part_Number: stm32g0_lqfp48_t2; Vendor: STMicroelectronics
footprint LQFP48
pins: 1 PC13 (io), 2 PC14-OSC32_IN (io), 3 PC15-OSC32_OUT (io), 4 VBAT (power), 5 VREF+ (power), 6 VDD/VDDA (power), 7 VSS/VSSA (power), 8 PF0-OSC_IN (io), 9 PF1-OSC_OUT (io), 10 NRST (io), 11 PA0 (io), 12 PA1 (io), 13 PA2 (io), 14 PA3 (io), 15 PA4 (io), 16 PA5 (io), 17 PA6 (io), 18 PA7 (io), 19 PB0 (io), 20 PB1 (io), 21 PB2 (io), 22 PB10 (io), 23 PB11 (io), 24 PB12 (io), 25 PB13 (io), 26 PB14 (io), 27 PB15 (io), 28 PA8 (io), 29 PA9 (io), 30 PC6 (io), 31 PC7 (io), 32 PA10 (io), 33 PA11 (io), 34 PA12 (io), 35 PA13 (io), 36 PA14-BOOT0 (io), 37 PA15 (io), 38 PD0 (io), 39 PD1 (io), 40 PD2 (io), 41 PD3 (io), 42 PB3 (io), 43 PB4 (io), 44 PB5 (io), 45 PB6 (io), 46 PB7 (io), 47 PB8 (io), 48 PB9 (io)

## STM32G081CBUx
designator U?
The STM32G081xB mainstream microcontrollers are based on high-performance Arm® Cortex®-M0+ 32-bit RISC core operating at up to 64 MHz frequency. / 128 Kbytes of Flash program memory and 36 Kbytes of SRAM. With 48pin UFQFPN 7x7x0.55 package; Manufacturer_Part_Number: stm32g0_ufqfpn48_t1; Built_By: EMA_Jessica; Vendor: STMicroelectronics
footprint UFQFPN48-7x7mm
part A pins: 1 PC13 (io), 2 PC14-OSC32_IN (io), 3 PC15-OSC32_OUT (io), 8 PF0-OSC_IN (io), 9 PF1-OSC_OUT (io), 10 PF2-NRST (io), 11 PA0 (io), 12 PA1 (io), 13 PA2 (io), 14 PA3 (io), 15 PA4 (io), 16 PA5 (io), 17 PA6 (io), 18 PA7 (io), 19 PB0 (io), 20 PB1 (io), 21 PB2 (io), 22 PB10 (io), 23 PB11 (io), 24 PB12 (io), 25 PB13 (io), 26 PB14 (io), 27 PB15 (io), 28 PA8 (io), 29 PA9 (io), 30 PC6 (io), 31 PC7 (io), 32 PA10 (io), 33 PA11[PA9] (io), 34 PA12[PA10] (io), 35 PA13 (io), 36 PA14-BOOT0 (io), 37 PA15 (io), 38 PD0 (io), 39 PD1 (io), 40 PD2 (io), 41 PD3 (io), 42 PB3 (io), 43 PB4 (io), 44 PB5 (io), 45 PB6 (io), 46 PB7 (io), 47 PB8 (io), 48 PB9 (io)
part B pins: 4 VBAT (power), 5 VREF+ (power), 6 VDD (power), 7 VSS (power), 49 EPAD

## STM32G081EBYx
designator U?
The STM32G081xB mainstream microcontrollers are based on high-performance Arm® Cortex®-M0+ 32-bit RISC core operating at up to 64 MHz frequency. / 128 Kbytes of Flash program memory and 36 Kbytes of SRAM. With 25pin WLCSP  2.3x2.5 package; Manufacturer_Part_Number: stm32g0_wlcsp25_t1; Built_By: EMA_Jessica; Vendor: STMicroelectronics
footprint WLCSP25
pins: A1 PA15 (io), A2 PA14-BOOT0 (io), A3 PB5 (io), A4 PB7 (io), A5 PC14-OSC32_IN (io), B1 PA12[PA10] (io), B2 PA13 (io), B3 PB6 (io), B4 PB8 (io), B5 PC15-OSC32_OUT (io), C1 PA11[PA9] (io), C2 PA6 (io), C3 PA3 (io), C4 PA0 (io), C5 VDD (power), D1 PA8 (io), D2 PA7 (io), D3 PA4 (io), D4 PA1 (io), D5 VSS (power), E1 PB1 (io), E2 PB0 (io), E3 PA5 (io), E4 PA2 (io), E5 PF2-NRST (io)

## STM32G081GBUx
designator U?
The STM32G081xB mainstream microcontrollers are based on high-performance Arm® Cortex®-M0+ 32-bit RISC core operating at up to 64 MHz frequency. / 128 Kbytes of Flash program memory and 36 Kbytes of SRAM. With 28pin UFQFPN 4x4x0.55 package; Manufacturer_Part_Number: stm32g0_ufqfpn28_t1; Built_By: EMA_Jessica; Vendor: STMicroelectronics
footprint UFQFPN-28
pins: 1 PC14-OSC32_IN (io), 2 PC15-OSC32_OUT (io), 3 VDD (power), 4 VSS (power), 5 PF2-NRST (io), 6 PA0 (io), 7 PA1 (io), 8 PA2 (io), 9 PA3 (io), 10 PA4 (io), 11 PA5 (io), 12 PA6 (io), 13 PA7 (io), 14 PB0 (io), 15 PB1 (io), 16 PA8 (io), 17 PC6 (io), 18 PA11[PA9] (io), 19 PA12[PA10] (io), 20 PA13 (io), 21 PA14-BOOT0 (io), 22 PA15 (io), 23 PB3 (io), 24 PB4 (io), 25 PB5 (io), 26 PB6 (io), 27 PB7 (io), 28 PB8 (io)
